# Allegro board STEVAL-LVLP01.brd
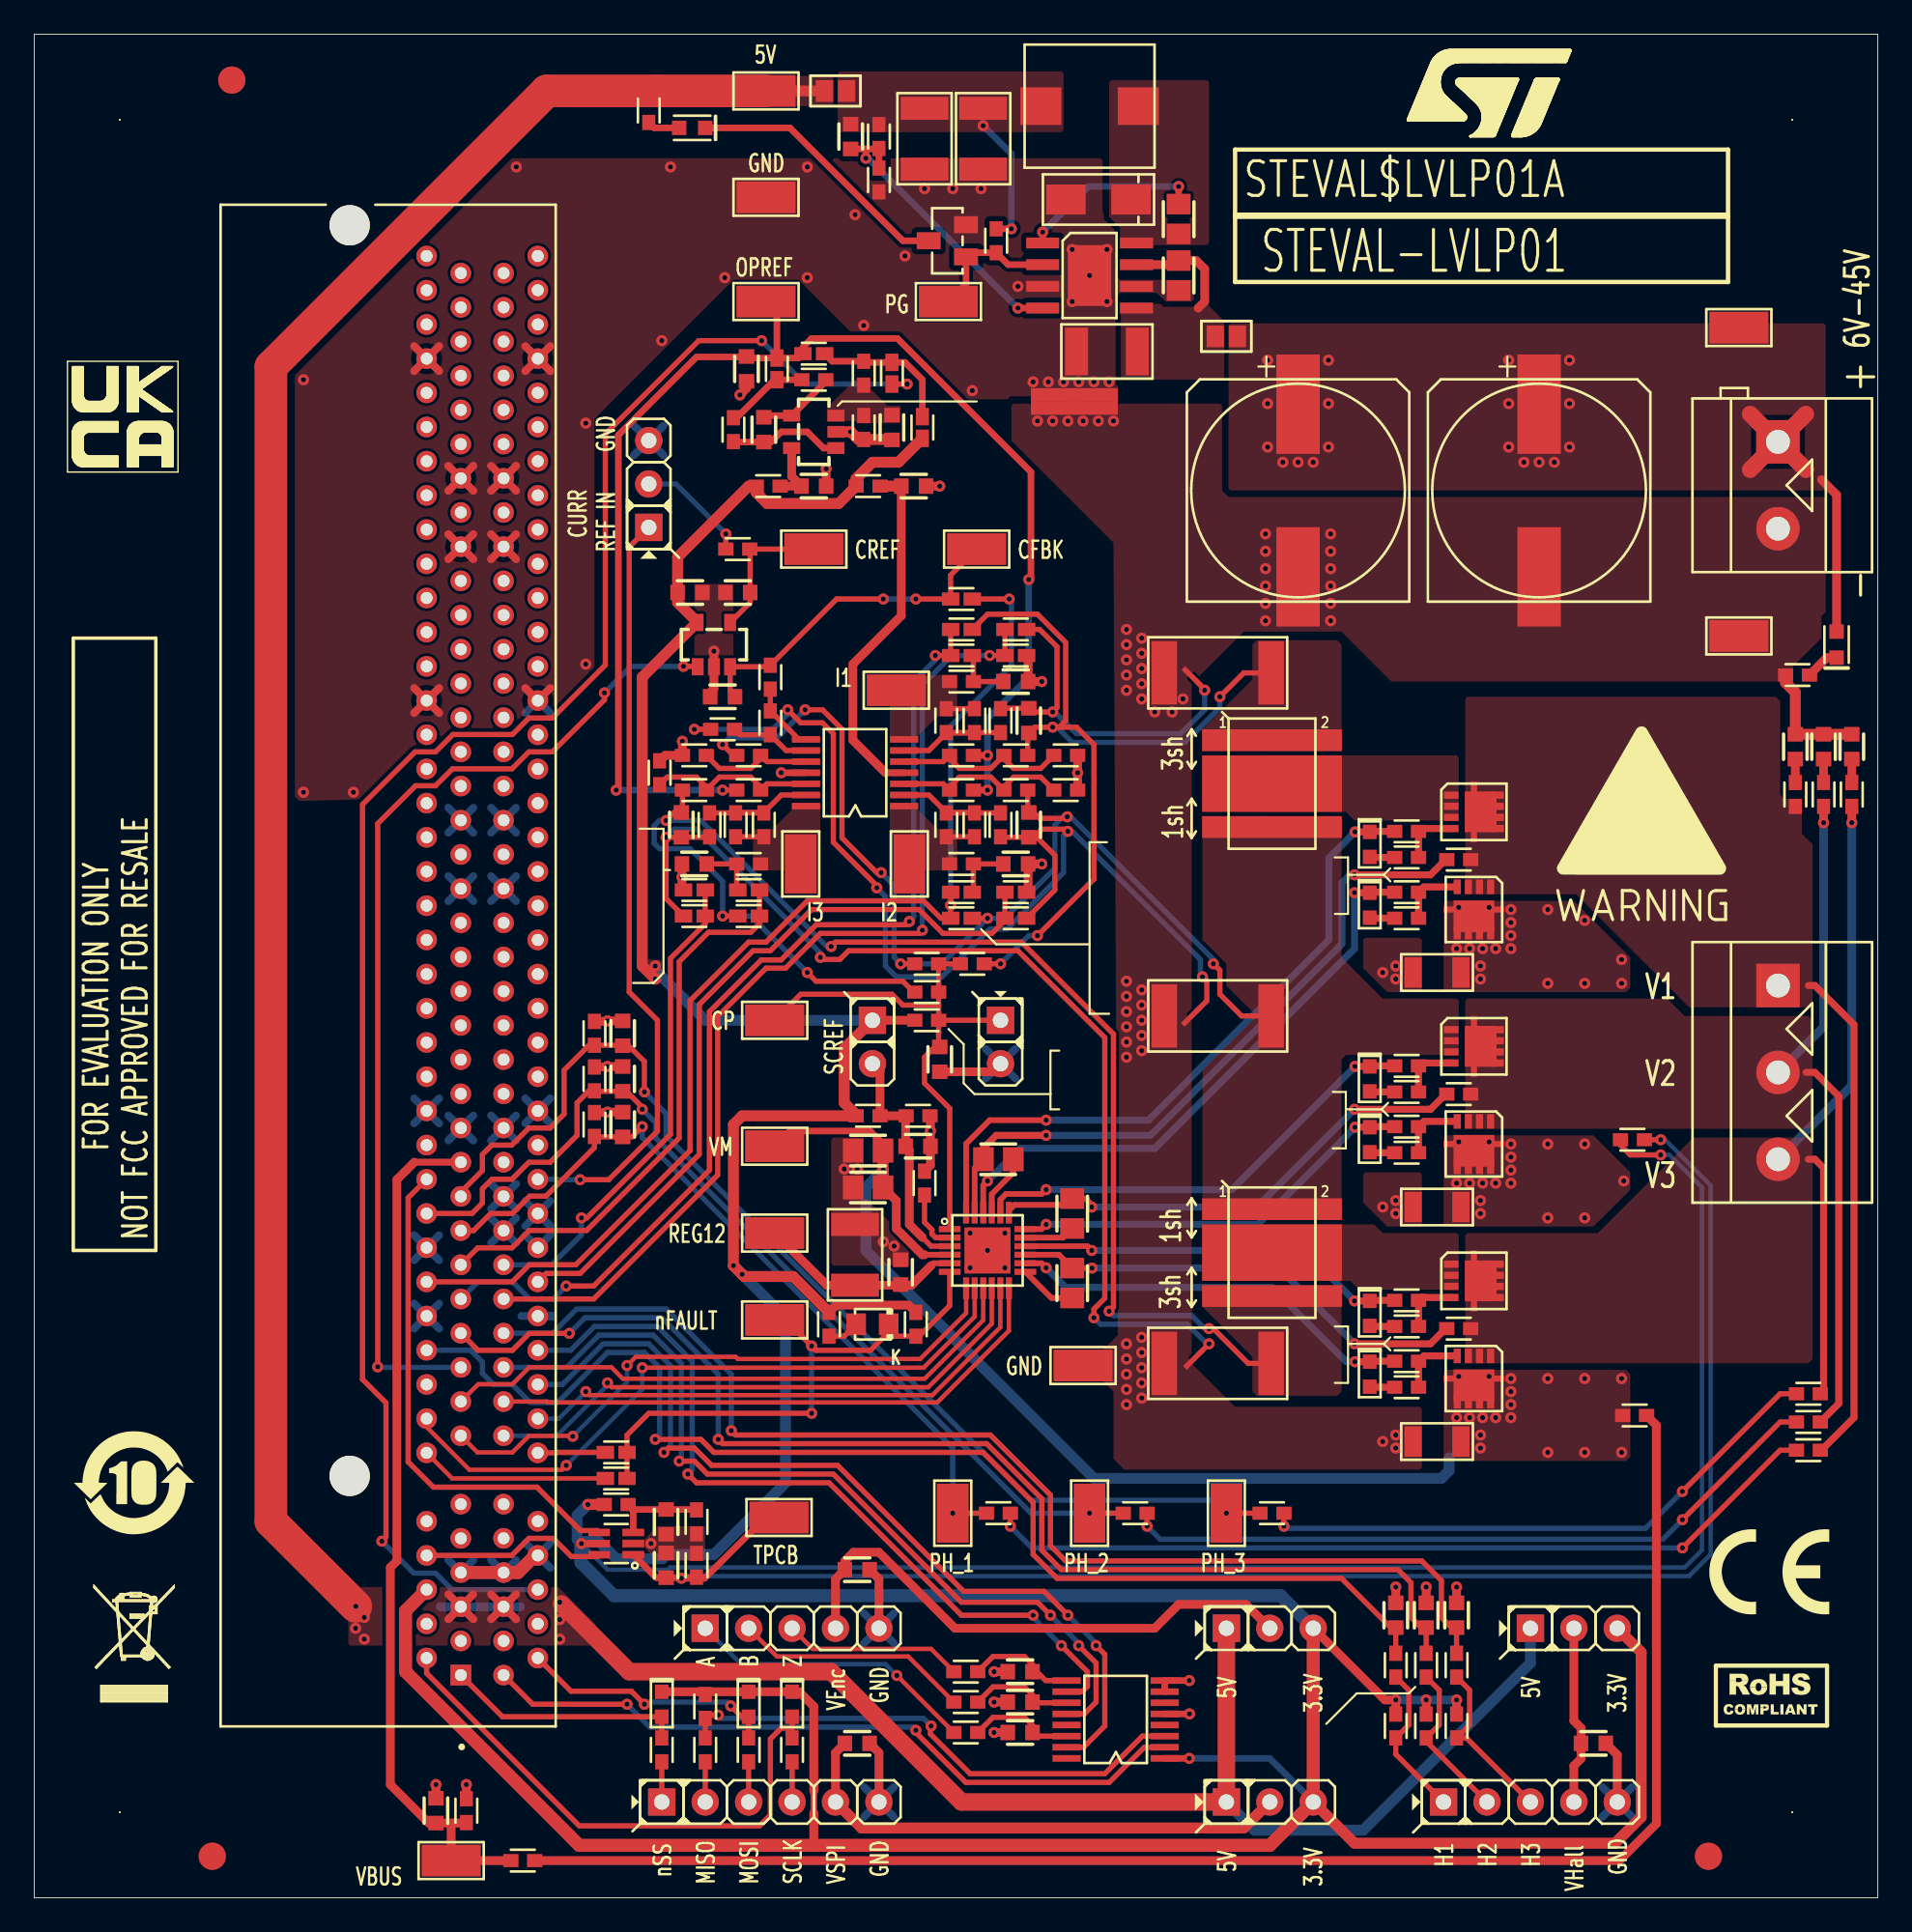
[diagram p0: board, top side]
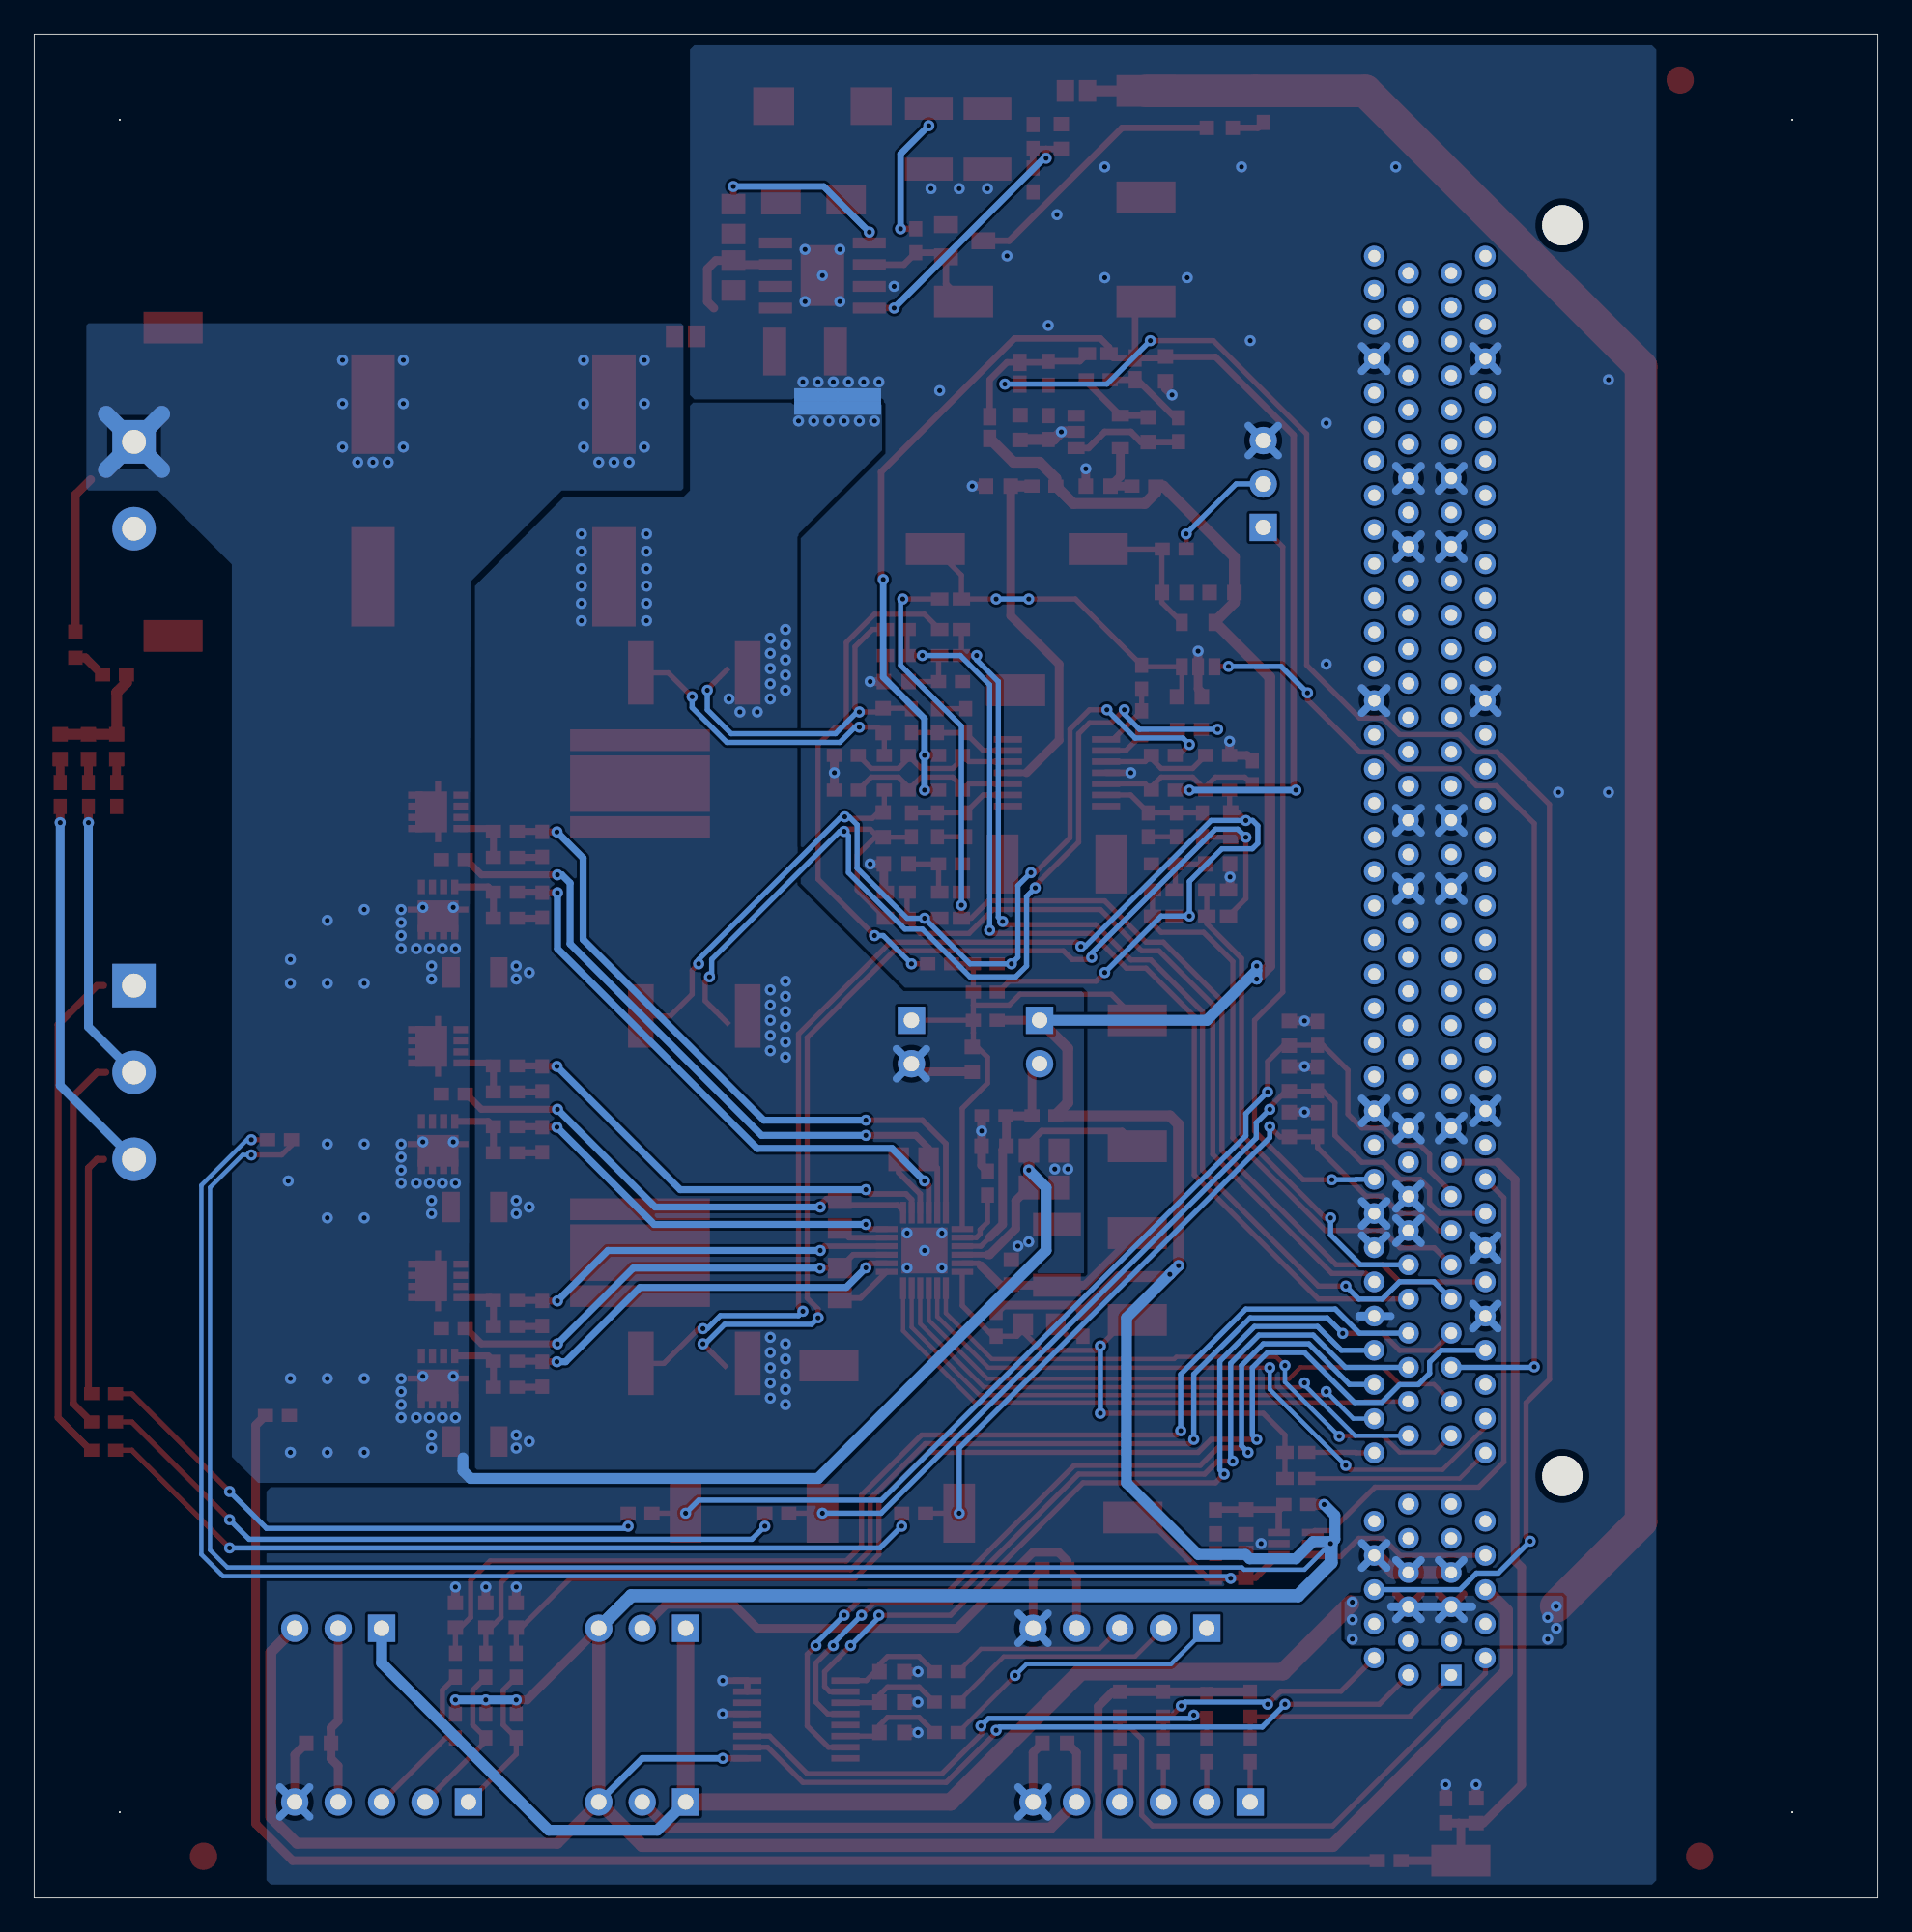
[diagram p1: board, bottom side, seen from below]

Outline 107.82 x 109 mm; copper layers: TOP, BOTTOM. Coordinates in mm from the lower left corner of the outline.
Outline path: 0,109 0,0 107.82,0 107.82,109 0,109

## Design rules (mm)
constraint set DEFAULT: min track width 0.2

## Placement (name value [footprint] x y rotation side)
C1  22uF  [C1210]  48.01 37.61 270 top
C2  220nF  [C0603]  50.67 36.59 90 top
C3  100nF  [C0805]  48.77 41.55 0 top
C4  1uF  [C0805]  48.77 43.71 0 top
C5  10nF  [C0603]  51.69 43.96 180 top
C6  1uF  [C0805]  56.39 43.2 0 top
C7  3.3nF  [C0603]  52.96 49.04 90 top
C8  1uF  [C0805]  60.71 35.96 90 top
C9  1uF  [C0805]  60.71 40.02 90 top
C10  220nF  [C1206]  82.04 54.12 90 top
C11  220nF  [C1206]  82.04 40.4 90 top
C12  220nF  [C1206]  82.04 26.69 90 top
C13  82nF  [C0603]  34.42 45.23 270 top
C14  82nF  [C0603]  34.42 47.9 270 top
C15  82nF  [C0603]  34.42 50.56 270 top
C16  NM  [C0603]  103 67.33 270 top
C17  NM  [C0603]  104.65 67.33 270 top
C18  NM  [C0603]  106.3 67.33 270 top
C19  100nF  [C0603]  51.44 82.57 0 top
C20  100nF  [C0603]  45.59 82.57 0 top
C21  1nF  [C0603]  58.17 68.85 270 top
C22  NM  [C0603]  57.4 71.14 180 top
C23  2.2u  [C0603]  41.66 89.43 270 top
C24  NM  [C0603]  50.16 86 270 top
C25  NM  [C0603]  42.67 85.87 90 top
C26  1nF  [C0603]  58.17 62.76 90 top
C27  NM  [C0603]  57.4 60.47 180 top
C28  100nF  [C0603]  38.35 76.34 0 top
C29  47p  [C0603]  40.26 70.25 0 top
C30  1nF  [C0603]  37.85 62.76 90 top
C31  10nF  [C0603]  41.15 76.34 0 top
C32  NM  [C0603]  38.61 60.47 0 top
C33  100nF  [C0805]  66.93 98.19 90 top
C34  47u  [C1210]  52.07 102.89 90 top
C35  47u  [C1210]  55.5 102.89 90 top
C36  1n  [C0603]  47.75 103.01 90 top
C37  100nF  [C0805]  66.93 94.89 270 top
C38  4.7uF  [C1210]  62.74 90.44 0 top
C39  47uF  [C-POL12_5X13_5]  88.01 82.31 0 top
C40  47uF  [C-POL12_5X13_5]  73.91 82.31 0 top
C41  82nF  [C0603]  23.5 5.1 270 top
C42  330nF  [C0603]  91.19 9.03 0 top
C43  2.2n  [C0603]  79.63 16.53 90 top
C44  2.2n  [C0603]  81.41 16.53 90 top
C45  2.2n  [C0603]  83.19 16.53 90 top
C46  1nF  [C0603]  57.66 9.67 0 top
C47  1nF  [C0603]  57.66 11.45 0 top
C48  330nF  [C0603]  48.13 19.19 0 top
C49  1nF  [C0603]  57.66 13.23 0 top
C50  10nF  [C0603]  36.96 19.45 270 top
C51  10nF  [C0603]  36.96 21.99 90 top
C52  330nF  [C0603]  48.13 9.03 0 top
D1  BAT30K  [SOD523]  78.11 58.06 270 top
D2  BAT30K  [SOD523]  78.11 44.34 270 top
D3  BAT30K  [SOD523]  78.11 30.62 270 top
D4  BAT30K  [SOD523]  78.11 61.61 270 top
D5  BAT30K  [SOD523]  78.11 47.9 270 top
D6  BAT30K  [SOD523]  78.11 34.18 270 top
D7  STPS2L60  [SMA]  62.24 99.33 270 top
D8  BAT30K  [SOD523]  36.7 11.32 270 top
D9  BAT30K  [SOD523]  41.78 11.32 270 top
D10  BAT30K  [SOD523]  44.32 11.32 270 top
J1  STRIP 1x2  [STRIP254P-M-2]  49.02 50.06 0 top
J2  STRIP 1x2  [STRIP254P-M-2]  56.52 50.06 0 top
J3  MORSV-508-3P_screw  [MORSV-508-3P]  101.98 48.28 270 top
J4  STRIP 1x3  [STRIP254P-M-3]  35.94 82.69 180 top
J5  STRIP 1x3  [STRIP254P-M-3]  90.04 15.77 90 top
J6  STRIP 1x5  [STRIP254P-M-5]  87.5 5.61 90 top
J7  MORSV-508-2P_screw  [MORSV-508-2P]  101.98 82.62 270 top
J8  STRIP 1x3  [STRIP254P-M-3]  72.26 15.77 90 top
J9  STRIP 1x5  [STRIP254P-M-5]  44.32 15.77 90 top
J10  STRIP 1x3  [STRIP254P-M-3]  72.26 5.61 90 top
J11  STRIP 1x6  [STRIP254P-M-6]  43.05 5.61 90 top
J12  PCIE-164-02-X-D-RA  [SAMTEC_PCIE-164-02-X-D-RA]  20.7 54.53 270 top
JP1  GND_node  [CORTONOSOLDER200MILS]  60.83 87.52 270 bottom
JP2  GND_node  [CORTONOSOLDER200MILS]  60.83 87.52 270 top
JP3  CurrentSense  [CURRENTSENSE-12]  67.73 71.41 315 top
JP4  CurrentSense  [CURRENTSENSE-12]  67.69 51.58 45 top
JP5  CurrentSense  [CURRENTSENSE-12]  67.82 31.51 45 top
L1  10uH  [CLF7045NI-D-TDK]  61.72 104.79 180 top
LED1  RED  [LED-0805]  49.02 33.55 180 top
LED2  GREEN  [LED-0603]  38.48 103.52 180 top
LED3  GREEN  [LED-0603]  105.41 73.3 90 top
NOREF  -  [unnamed]  10.41 2.43 0 top
NOREF#2  -  [unnamed]  11.56 106.32 0 top
NOREF#3  -  [#2]  101.52 11.82 0 top
NOREF#4  -  [#2]  -0.25 -84.82 0 top
NOREF#5  -  [unnamed]  97.92 2.43 0 top
NOREF#6  -  [#2]  93.98 60.6 0 top
NOREF#7  -  [#2]  97.98 16.58 0 top
NOREF#8  -  [unnamed]  5 104 90 top
NOREF#9  -  [#2]  2.32 21.26 0 top
NOREF#10  -  [#2]  217.55 28.21 0 top
NOREF#11  -  [#2]  107.82 0 90 top
NOREF#12  -  [#2]  0 109 0 top
NOREF#13  -  [unnamed]  5 5 90 top
NOREF#14  -  [unnamed]  102.82 5 90 top
NOREF#15  -  [unnamed]  102.82 104 90 top
NOREF#16  -  [#2]  80.25 103.4 0 top
NOREF#17  -  [#2]  132.72 56.41 0 top
NOREF#18  -  [#2]  5.8 15.73 0 top
NTC1  10k  [R0603]  93.47 44.34 90 top
Q1  STL8N10F7  [PFLAT_3_3X3_3]  84.2 57.8 270 top
Q2  STL8N10F7  [PFLAT_3_3X3_3]  84.2 44.09 270 top
Q3  STL8N10F7  [PFLAT_3_3X3_3]  84.2 30.37 270 top
Q4  STL8N10F7  [PFLAT_3_3X3_3]  84.2 63.52 0 top
Q5  STL8N10F7  [PFLAT_3_3X3_3]  84.2 49.8 0 top
Q6  STL8N10F7  [PFLAT_3_3X3_3]  84.2 36.09 0 top
Q7  BSS123  [SOT23]  53.4 96.92 90 top
R1  33k  [R0603]  48.77 45.74 270 top
R2  470  [R0603]  46.48 33.55 180 top
R3  39k  [R0603]  51.56 33.55 180 top
R4  12k  [R0603]  51.69 45.74 270 top
R5  0  [R0603]  52.07 41.8 0 top
R6  5.1k  [R0603]  52.2 51.33 90 top
R7  2.2k  [R0603]  54.86 54.63 90 top
R8  2.2k  [R0603]  52.2 54.63 270 top
R9  2.2k  [R0603]  52.2 52.98 270 top
R10  100  [R0603]  80.26 58.82 90 top
R11  100  [R0603]  80.26 45.1 90 top
R12  100  [R0603]  80.26 31.39 90 top
R13  39  [R0603]  80.26 57.29 90 top
R14  39  [R0603]  80.26 43.58 90 top
R15  39  [R0603]  80.26 29.86 90 top
R16  0  [R0603]  83.31 60.72 90 top
R17  0  [R0603]  83.31 47.01 90 top
R18  0  [R0603]  83.31 33.29 90 top
R19  100  [R0603]  80.26 62.37 90 top
R20  100  [R0603]  80.26 48.66 90 top
R21  100  [R0603]  80.26 34.94 90 top
R22  39  [R0603]  80.26 60.85 90 top
R23  39  [R0603]  80.26 47.13 90 top
R24  39  [R0603]  80.26 33.42 90 top
R25  15m  [R2512]  69.22 71.65 0 top
R26  15m  [R2512]  69.22 51.58 0 top
R27  15m  [R2512]  69.22 31.26 0 top
R28  68k  [R0603]  103.76 26.18 270 top
R29  27k  [R0603]  56.39 22.5 270 top
R30  68k  [R0603]  103.76 27.83 270 top
R31  27k  [R0603]  64.39 22.5 270 top
R32  68k  [R0603]  103.76 29.48 270 top
R33  27k  [R0603]  72.39 22.5 270 top
R34  NM  [R0603]  103 64.53 0 top
R35  3.9k  [R0603]  32.77 45.23 0 top
R36  NM  [R0603]  104.65 64.53 0 top
R37  3.9k  [R0603]  32.77 47.9 0 top
R38  NM  [R0603]  106.3 64.53 0 top
R39  3.9k  [R0603]  32.77 50.56 0 top
R40  4.7  [R0603]  48.77 82.57 90 top
R41  4.7  [R0603]  42.93 82.57 90 top
R42  30k  [R0603]  54.23 66.82 270 top
R43  0R  [J0603]  54.23 74.19 270 top
R44  1k  [R0603]  57.4 66.82 90 top
R45  0  [R0603]  54.23 71.14 270 top
R46  NM  [J0603]  54.23 72.66 270 top
R47  1k  [R0603]  56.52 68.85 180 top
R48  30k  [R0603]  60.33 66.82 90 top
R49  NM  [J0603]  57.4 72.66 90 top
R50  NM  [J0603]  50.16 89.17 0 top
R51  0R  [J0603]  51.94 86 0 top
R52  0  [J0603]  45.59 90.31 270 top
R53  30k  [R0603]  54.99 68.85 0 top
R54  0R  [J0603]  57.4 74.19 90 top
R55  NM  [R0603]  48.51 89.17 180 top
R56  30k  [R0603]  53.34 68.85 0 top
R57  NM  [J0603]  43.43 89.43 0 top
R58  NM  [R0603]  40.89 85.87 180 top
R59  NM  [R0603]  48.51 86 180 top
R60  NM  [J0603]  54.23 75.96 90 top
R61  30k  [R0603]  54.23 64.79 270 top
R62  0R  [J0603]  54.23 57.29 270 top
R63  1k  [R0603]  57.4 64.79 90 top
R64  0  [R0603]  54.23 60.47 270 top
R65  NM  [J0603]  54.23 58.82 270 top
R66  NM  [R0603]  45.59 88.79 90 top
R67  1k  [R0603]  56.52 62.76 0 top
R68  30k  [R0603]  60.33 64.79 90 top
R69  NM  [J0603]  57.4 58.82 90 top
R70  30k  [R0603]  53.34 62.76 180 top
R71  0R  [J0603]  57.4 57.29 90 top
R72  30k  [R0603]  54.99 62.76 180 top
R73  1k  [R0603]  41.78 66.82 270 top
R74  10k  [R0603]  43.05 71.39 0 top
R75  1k  [R0603]  40.26 68.34 270 top
R76  22k  [R0603]  38.61 66.82 270 top
R77  22k  [R0603]  43.05 68.72 180 top
R78  30k  [R0603]  41.78 64.79 90 top
R79  0R  [J0603]  41.78 57.42 90 top
R80  1k  [R0603]  38.61 64.79 270 top
R81  10k  [R0603]  41.15 78.88 270 top
R82  0  [R0603]  41.78 60.47 90 top
R83  NM  [J0603]  41.78 58.95 90 top
R84  1k  [R0603]  39.5 62.76 0 top
R85  30k  [R0603]  36.58 65.8 180 top
R86  NM  [J0603]  38.61 58.95 270 top
R87  30k  [R0603]  41.02 62.76 180 top
R88  0R  [J0603]  38.61 57.42 270 top
R89  30k  [R0603]  42.67 62.76 180 top
R90  0R  [J0805]  69.72 91.33 90 top
R91  47k  [R0603]  56.26 96.92 180 top
R92  0R  [J0805]  46.86 105.68 270 top
R93  4.7k  [R0603]  49.4 103.01 180 top
R94  1k  [R0603]  35.94 104.54 180 top
R95  1.5k  [R0603]  49.4 100.47 180 top
R96  4.7k  [R0603]  79.63 10.05 180 top
R97  4.7k  [R0603]  81.41 10.05 180 top
R98  4.7k  [R0603]  83.19 10.05 180 top
R99  68k  [R0603]  93.6 28.21 90 top
R100  27k  [R0603]  28.57 2.18 270 top
R101  3.3k  [R0603]  79.63 13.61 0 top
R102  3.3k  [R0603]  81.41 13.61 0 top
R103  3.9k  [R0603]  25.27 5.1 0 top
R104  3.3k  [R0603]  83.19 13.61 0 top
R105  15k  [R0603]  103.12 71.52 90 top
R106  330  [R0603]  54.48 9.67 270 top
R107  330  [R0603]  54.48 11.45 270 top
R108  330  [R0603]  54.48 13.23 270 top
R109  910  [R0603]  38.73 19.45 0 top
R110  22k  [R0603]  34.04 23 270 top
R111  10k  [R0603]  38.73 21.99 180 top
R112  22k  [R0603]  39.24 11.19 0 top
R113  100  [R0603]  36.7 8.65 0 top
R114  100  [R0603]  39.24 8.65 0 top
R115  100  [R0603]  41.78 8.65 0 top
R116  100  [R0603]  44.32 8.65 0 top
R117  NM  [J0603]  34.04 24.53 90 top
R118  0R  [J0603]  34.04 26.05 270 top
SB1  Power_Solder_Bridge  [254-PITCH_HEADER-2X3-JUMP]  72.39 65.17 0 top
SB2  Power_Solder_Bridge  [254-PITCH_HEADER-2X3-JUMP]  72.39 37.74 0 top
TP1  TP-SMD-S1751-46R  [S1751-46R]  43.31 38.88 180 top
TP2  TP-SMD-S1751-46R  [S1751-46R]  43.31 43.96 180 top
TP3  TP-SMD-S1751-46R  [S1751-46R]  43.31 33.8 0 top
TP4  TP-SMD-S1751-46R  [S1751-46R]  43.31 51.33 180 top
TP5  TP-SMD-S1751-46R  [S1751-46R]  61.34 31.13 0 top
TP6  TP-SMD-S1751-46R  [S1751-46R]  53.72 22.5 90 top
TP7  TP-SMD-S1751-46R  [S1751-46R]  61.72 22.5 90 top
TP8  TP-SMD-S1751-46R  [S1751-46R]  69.72 22.5 90 top
TP9  TP-SMD-S1751-46R  [S1751-46R]  50.42 70.63 180 top
TP10  TP-SMD-S1751-46R  [S1751-46R]  42.8 93.36 0 top
TP11  TP-SMD-S1751-46R  [S1751-46R]  51.18 60.47 270 top
TP12  TP-SMD-S1751-46R  [S1751-46R]  55.12 78.88 180 top
TP13  TP-SMD-S1751-46R  [S1751-46R]  44.83 60.47 270 top
TP14  TP-SMD-S1751-46R  [S1751-46R]  45.59 78.88 180 top
TP15  TP-SMD-S1751-46R  [S1751-46R]  42.8 105.68 180 top
TP16  TP-SMD-S1751-46R  [S1751-46R]  42.8 99.46 0 top
TP17  TP-SMD-S1751-46R  [S1751-46R]  53.47 93.36 0 top
TP18  TP-SMD-S1751-46R  [S1751-46R]  99.69 91.84 0 top
TP19  TP-SMD-S1751-46R  [S1751-46R]  24.38 2.18 0 top
TP20  TP-SMD-S1751-46R  [S1751-46R]  99.69 73.8 0 top
TP21  TP-SMD-S1751-46R  [S1751-46R]  43.56 22.24 0 top
U1  STDRIVE101  [QFN24-4X4]  55.75 37.86 270 top
U2  TSV994  [TSSOP14]  48.01 65.8 180 top
U3  NM  [SOT23-5L]  45.59 85.74 90 top
U4  TS3021ILT  [SOT23-5L]  39.75 73.3 0 top
U5  ST1S14PHR  [SO8-EP-9]  61.72 94.89 0 top
U6  CD74HC4050  [TSSOP16]  63.25 10.43 180 top
U7  Value  [SOT323-6L]  34.04 20.72 90 top

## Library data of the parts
C1 C34 C35 C38 = C-1210
C2 C5 C7 C13-C32 C36 C41-C52 = C-0603
C3 C6 C8 C9 C33 C37 = C-0805
C4 C10-C12 = C-1206
C39 C40 = C_EL-DIAM10
D1-D6 D8-D10 = BAT30K
D7 = STPS2L30A
J1 J2 = STRIP 1x2
J3 = MORSV-508-3P_screw
J4 J5 J8 J10 = STRIP 1x3
J6 J9 = STRIP 1x5
J7 = MORSV-508-2P_screw_0
J11 = STRIP 1x6
J12 = PCIE-164-02-X-D-RA
JP1-JP5 = CurrentSense
L1 = INDUCTOR
LED1 = LED-0805
LED2 LED3 = LED-0603-GREEN-WE
NTC1 = NTC-NCP18XH103F03RB
Q1-Q6 = STL11N6F7
Q7 = BSS123
R1-R24 R28-R42 R44 R45 R47 R48 R53 R55 R56 R58 R59 R61 R63 R64 R66-R68 R70 R72-R78 R80-R82 R84 R85 R87 R89 R91 R93-R116 = R-0603
R25-R27 = R-2512
R43 R46 R49-R52 R54 R57 R60 R62 R65 R69 R71 R79 R83 R86 R88 R117 R118 = JUMPER-R0603
R90 R92 = JUMPER-R0805
SB1 SB2 = Power_Solder_Bridge
TP1-TP21 = TP-SMD-S1751-46R
U1 = STDRIVE101
U2 = TSV994IPT
U3 = TS461CLT
U4 = TS3021ILT
U5 = ST1S14PHR
U6 = CD74HC4050PW
U7 = STG3157CTR

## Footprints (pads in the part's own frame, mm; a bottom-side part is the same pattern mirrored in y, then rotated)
254-PITCH_HEADER-2X3-JUMP
  rect 8.179x1.27 smd: 1(0,2.54) 3(0,-2.54)
  rect 8.179x3.302 smd: 2(0,0)
C0603
  rect 0.85x0.9 smd: 1(-0.725,0) 2(0.725,0)
C0805
  rect 1.2x1.4 smd: 1(-0.875,0) 2(0.875,0)
C1206
  rect 1.778x1.016 smd: 1(0,1.397) 2(0,-1.397)
C1210
  rect 1.346x2.794 smd: 1(-1.778,0) 2(1.778,0)
C-POL12_5X13_5
  rect 2.54x5.817 smd: 1(0,5.05) 2(0,-5.05)
CLF7045NI-D-TDK
  rect 2.4x2.2 smd: 1(-2.85,0) 2(2.85,0)
CORTONOSOLDER200MILS
  rect 0.787x5.08 smd: 1(-0.127,0) 2(0.127,0)
CURRENTSENSE-12
  rect 0.762x0.305 smd: 1(-0.356,0) 2(0.356,0)
J0603
  rect 0.762x1.016 smd: 1(0,0.635) 2(0,-0.635)
J0805
  rect 1.27x1.016 smd: 1(0,0.648) 2(0,-0.648)
LED-0603
  rect 0.838x0.838 smd: 1(-0.762,0) 2(0.762,0)
LED-0805
  rect 1.143x1.27 smd: 1(-0.953,0) 2(0.953,0)
MORSV-508-2P
  rect 2.54x2.54 hole 1.397: 1(-2.54,0)
  round 2.54 hole 1.397: 2(2.54,0)
MORSV-508-3P
  rect 2.54x2.54 hole 1.397: 1(-5.08,0)
  round 2.54 hole 1.397: 2(0,0) 3(5.08,0)
PFLAT_3_3X3_3
  rect 0.85x0.42 smd: 1(-1.325,0.975) 2(-1.325,0.325) 3(-1.325,-0.325) 4(-1.325,-0.975) 5(1.325,-0.975) 6(1.325,-0.325) 7(1.325,0.325) 8(1.325,0.975)
QFN24-4X4
  rect 0.356x1.27 smd: 1(-1.25,-2.21) 2(-0.75,-2.21) 3(-0.25,-2.21) 4(0.25,-2.21) 5(0.75,-2.21) 6(1.25,-2.21) 13(1.25,2.21) 14(0.75,2.21) 15(0.25,2.21) 16(-0.25,2.21) 17(-0.75,2.21) 18(-1.25,2.21)
  rect 1.27x0.356 smd: 7(2.21,-1.25) 8(2.21,-0.75) 9(2.21,-0.25) 10(2.21,0.25) 11(2.21,0.75) 12(2.21,1.25) 19(-2.21,1.25) 20(-2.21,0.75) 21(-2.21,0.25) 22(-2.21,-0.25) 23(-2.21,-0.75) 24(-2.21,-1.25)
  rect 2.692x2.692 smd: 25(0,0)
R0603
  rect 0.762x0.889 smd: 1(0,0.699) 2(0,-0.699)
R2512
  rect 1.499x3.708 smd: 1(-3.124,0) 2(3.124,0)
S1751-46R
  rect 3.454x1.854 smd: 1(0,0)
SAMTEC_PCIE-164-02-X-D-RA
  round 2.35 hole 2.35 unplated: (-43.3,-2.25) (29.85,-2.25)
  rect 1.208x1.208 hole 0.7: A01(41.5,4.25)
  round 1.208 hole 0.7: A02(40.5,2.25) A03(39.5,4.25) A04(38.5,2.25) A05(37.5,4.25) A06(36.5,2.25) A07(35.5,4.25) A08(34.5,2.25) A09(33.5,4.25) A10(32.5,2.25) A11(31.5,4.25) A12(28.5,2.25) A13(27.5,4.25) A14(26.5,2.25) A15(25.5,4.25) A16(24.5,2.25) A17(23.5,4.25) A18(22.5,2.25) A19(21.5,4.25) A20(20.5,2.25) A21(19.5,4.25) A22(18.5,2.25) A23(17.5,4.25) A24(16.5,2.25) A25(15.5,4.25) A26(14.5,2.25) A27(13.5,4.25) A28(12.5,2.25) A29(11.5,4.25) A30(10.5,2.25) A31(9.5,4.25) A32(8.5,2.25) A33(7.5,4.25) A34(6.5,2.25) A35(5.5,4.25) A36(4.5,2.25) A37(3.5,4.25) A38(2.5,2.25) A39(1.5,4.25) A40(0.5,2.25) A41(-0.5,4.25) A42(-1.5,2.25) A43(-2.5,4.25) A44(-3.5,2.25) A45(-4.5,4.25) A46(-5.5,2.25) A47(-6.5,4.25) A48(-7.5,2.25) A49(-8.5,4.25) A50(-9.5,2.25) A51(-10.5,4.25) A52(-11.5,2.25) A53(-12.5,4.25) A54(-13.5,2.25) A55(-14.5,4.25) A56(-15.5,2.25) A57(-16.5,4.25) A58(-17.5,2.25) A59(-18.5,4.25) A60(-19.5,2.25) A61(-20.5,4.25) A62(-21.5,2.25) A63(-22.5,4.25) A64(-23.5,2.25) A65(-24.5,4.25) A66(-25.5,2.25) A67(-26.5,4.25) A68(-27.5,2.25) A69(-28.5,4.25) A70(-29.5,2.25) A71(-30.5,4.25) A72(-31.5,2.25) A73(-32.5,4.25) A74(-33.5,2.25) A75(-34.5,4.25) A76(-35.5,2.25) A77(-36.5,4.25) A78(-37.5,2.25) A79(-38.5,4.25) A80(-39.5,2.25) A81(-40.5,4.25) A82(-41.5,2.25) B01(41.5,6.75) B02(40.5,8.75) B03(39.5,6.75) B04(38.5,8.75) B05(37.5,6.75) B06(36.5,8.75) B07(35.5,6.75) B08(34.5,8.75) B09(33.5,6.75) B10(32.5,8.75) B11(31.5,6.75) B12(28.5,8.75) B13(27.5,6.75) B14(26.5,8.75) B15(25.5,6.75) B16(24.5,8.75) B17(23.5,6.75) B18(22.5,8.75) B19(21.5,6.75) B20(20.5,8.75) B21(19.5,6.75) B22(18.5,8.75) B23(17.5,6.75) B24(16.5,8.75) B25(15.5,6.75) B26(14.5,8.75) B27(13.5,6.75) B28(12.5,8.75) B29(11.5,6.75) B30(10.5,8.75) B31(9.5,6.75) B32(8.5,8.75) B33(7.5,6.75) B34(6.5,8.75) B35(5.5,6.75) B36(4.5,8.75) B37(3.5,6.75) B38(2.5,8.75) B39(1.5,6.75) B40(0.5,8.75) B41(-0.5,6.75) B42(-1.5,8.75) B43(-2.5,6.75) B44(-3.5,8.75) B45(-4.5,6.75) B46(-5.5,8.75) B47(-6.5,6.75) B48(-7.5,8.75) B49(-8.5,6.75) B50(-9.5,8.75) B51(-10.5,6.75) B52(-11.5,8.75) B53(-12.5,6.75) B54(-13.5,8.75) B55(-14.5,6.75) B56(-15.5,8.75) B57(-16.5,6.75) B58(-17.5,8.75) B59(-18.5,6.75) B60(-19.5,8.75) B61(-20.5,6.75) B62(-21.5,8.75) B63(-22.5,6.75) B64(-23.5,8.75) B65(-24.5,6.75) B66(-25.5,8.75) B67(-26.5,6.75) B68(-27.5,8.75) B69(-28.5,6.75) B70(-29.5,8.75) B71(-30.5,6.75) B72(-31.5,8.75) B73(-32.5,6.75) B74(-33.5,8.75) B75(-34.5,6.75) B76(-35.5,8.75) B77(-36.5,6.75) B78(-37.5,8.75) B79(-38.5,6.75) B80(-39.5,8.75) B81(-40.5,6.75) B82(-41.5,8.75)
SMA
  rect 1.753x2.311 smd: 1(0,1.905) 2(0,-1.905)
SO8-EP-9
  rect 1.93x0.635 smd: 1(-2.743,1.905) 2(-2.743,0.635) 3(-2.743,-0.635) 4(-2.743,-1.905) 5(2.743,-1.905) 6(2.743,-0.635) 7(2.743,0.635) 8(2.743,1.905)
  rect 2.54x3.556 smd: 9(0,0)
SOD523
  rect 0.838x0.8 smd: 1(-0.731,0) 2(0.731,0)
SOT23
  rect 0.991x1.397 smd: 1(-0.94,-1.092) 2(0.94,-1.092) 3(0,1.092)
SOT23-5L
  rect 0.69x1 smd: 1(-0.95,-1.295) 2(0,-1.295) 3(0.95,-1.295) 4(0.95,1.295) 5(-0.95,1.295)
SOT323-6L
  rect 0.432x1.27 smd: 1(-0.65,-1) 2(0,-1) 3(0.65,-1) 4(0.65,1) 5(0,1) 6(-0.65,1)
STRIP254P-M-2
  rect 1.6x1.6 hole 0.9: 1(0,1.27)
  round 1.6 hole 0.9: 2(0,-1.27)
STRIP254P-M-3
  rect 1.6x1.6 hole 0.9: 1(0,2.54)
  round 1.6 hole 0.9: 2(0,0) 3(0,-2.54)
STRIP254P-M-5
  rect 1.6x1.6 hole 0.9: 1(0,5.08)
  round 1.6 hole 0.9: 2(0,2.54) 3(0,0) 4(0,-2.54) 5(0,-5.08)
STRIP254P-M-6
  rect 1.6x1.6 hole 0.9: 1(0,6.35)
  round 1.6 hole 0.9: 2(0,3.81) 3(0,1.27) 4(0,-1.27) 5(0,-3.81) 6(0,-6.35)
TSSOP14
  rect 1.651x0.381 smd: 1(-2.87,1.951) 2(-2.87,1.3) 3(-2.87,0.65) 4(-2.87,0) 5(-2.87,-0.65) 6(-2.87,-1.3) 7(-2.87,-1.951) 8(2.87,-1.951) 9(2.87,-1.3) 10(2.87,-0.65) 11(2.87,0) 12(2.87,0.65) 13(2.87,1.3) 14(2.87,1.951)
TSSOP16
  rect 1.651x0.381 smd: 1(-2.87,2.276) 2(-2.87,1.626) 3(-2.87,0.975) 4(-2.87,0.325) 5(-2.87,-0.325) 6(-2.87,-0.975) 7(-2.87,-1.626) 8(-2.87,-2.276) 9(2.87,-2.276) 10(2.87,-1.626) 11(2.87,-0.975) 12(2.87,-0.325) 13(2.87,0.325) 14(2.87,0.975) 15(2.87,1.626) 16(2.87,2.276)
unnamed
  round 1.6 smd: (0,0)

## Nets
5V: J5.1 J8.1 J10.1 J12.A05 J12.B05 R92.2 R94.2 TP15.1
12V: C1.2 C2.1 TP1.1 U1.5
GND: C1.1 C2.2 C3.1 C4.1 C5.1 C7.1 C10.1 C11.1 C12.1 C16.1 C17.1 C18.1 C39.2 C40.2 J2.2 J7.2 JP1.2 JP2.2 JP3.1 JP4.1 JP5.1 R4.1 R5.1 R25.1 R26.1 R27.1 R105.1 TP5.1 TP20.1 U1.25
GND_SIGNAL: C13.1 C14.1 C15.1 C19.2 C20.2 C22.1 C23.2 C24.2 C27.1 C28.2 C29.1 C31.1 C32.1 C34.1 C35.1 C37.2 C38.1 C41.1 C42.2 C43.2 C44.2 C45.2 C46.1 C47.1 C48.2 C49.1 C50.1 C51.1 C52.2 D7.2 J4.3 J6.5 J9.5 J11.6 J12.A07 J12.A20 J12.A24 J12.A31 J12.A32 J12.A45 J12.A49 J12.A56 J12.A65 J12.A69 J12.A76 J12.B07 J12.B08 J12.B20 J12.B24 J12.B25 J12.B26 J12.B27 J12.B31 J12.B32 J12.B45 J12.B49 J12.B56 J12.B65 J12.B69 J12.B76 JP1.1 JP2.1 Q7.2(SOURCE) R35.1 R37.1 R39.1 R48.2 R49.2 R59.1 R68.2 R69.2 R76.2 R85.2 R86.2 R95.1 R103.1 R109.1 R111.1 TP16.1 U2.11 U3.2(V-) U4.2(VCC-) U5.3 U5.6 U5.9 U6.5 U6.7 U6.8 U7.2
V1: J3.1 Q1.1 Q1.2 Q1.3(S#3) Q4.5 Q4.6 Q4.7 Q4.8 R16.2 R28.1 R34.2
V2: J3.2 Q2.1 Q2.2 Q2.3(S#3) Q5.5 Q5.6 Q5.7 Q5.8 R17.2 R30.1 R36.2
V3: J3.3 Q3.1 Q3.2 Q3.3(S#3) Q6.5 Q6.6 Q6.7 Q6.8 R18.2 R32.1 R38.2
VBUS: C41.2 J12.A29 R100.2 R103.2 TP19.1
VDD: C28.1 D8.1(C) D9.1(C) D10.1(C) J1.1 J5.3 J8.3 J10.3 J12.A06 NTC1.1 R1.2 R2.2 R3.2 R6.1 R40.1 R41.1 R51.2 R96.2 R97.2 R98.2 R110.2 R112.1 U4.5 U6.1 U7.5(VCC)
VDD_C: C20.1 R41.2 U3.5
VDD_F: C19.1 R40.2 U2.4
BUCK_OUT: C34.2 C35.2 C36.2 L1.2 R91.2 R92.1 R93.2
CFBK: C29.2 R60.1 R74.1 TP12.1 U4.3
CP_DRV: C7.2 J2.1 R6.2 R7.1 R8.1 R9.1 TP4.1 U1.1
CURR_REF: J4.1 J12.B28
ENCA: J12.B16 U6.15(6Y)
ENCB: J12.B17 U6.12
ENCZ: J12.B18 U6.10
ETR: J12.A17 U4.1
FB: C36.1 R93.1 R95.2 U5.4
GHS1: D1.1(C) R10.1 U1.22
GHS2: D2.1(C) R11.1 U1.18
GHS3: D3.1(C) R12.1 U1.14
GLS1: D4.1(C) R19.1 U1.24
GLS2: D5.1(C) R20.1 U1.20
GLS3: D6.1(C) R21.1 U1.16
H1: C43.1 J12.A18 R101.1
H2: C44.1 J12.A19 R102.1
H3: C45.1 J12.B19 R104.1
ID_ENABLE_N: J12.A08 U7.6
INH1: J12.A13 U1.7
INH2: J12.A14 U1.8
INH3: J12.A15 U1.9
INL1: J12.B13 U1.10
INL2: J12.B14 U1.11
INL3: J12.B15 U1.12
ISNS1N: J12.B21 R49.1 R54.1
ISNS1P: J12.A21 R43.2 R46.2
ISNS2N: J12.B22 R69.1 R71.1
ISNS2P: J12.A22 R60.2 R62.2 R65.2
ISNS3N: J12.B23 R86.1 R88.1
ISNS3P: J12.A23 R79.2 R83.2
LSS1: Q4.1 Q4.2 Q4.3(S#3) SB1.2
LSS3: Q6.1 Q6.2 Q6.3(S#3) SB2.2
NFAULT: LED1.1 R3.1 R117.2 R118.1 TP3.1 U1.6
OPREF: C23.1 R42.1 R52.2 R57.1 R61.1 R78.1 TP10.1
OUT1: C6.1 R16.1 U1.23
OUT2: C9.2 R17.1 U1.19
OUT3: C8.2 R18.1 U1.15
P_GOOD: Q7.1 R91.1 TP17.1 U5.2
SCREF: C5.2 J1.2 R1.1 R4.2 U1.3
SHUNT1N: C21.1 JP3.2 R47.2 R54.2
SHUNT1P: C21.2 R7.2 R25.2 R43.1 R44.2 SB1.1
SHUNT2N: C26.1 JP4.2 R67.2 R71.2 R75.2
SHUNT2P: C26.2 Q5.1 Q5.2 Q5.3(S#3) R8.2 R26.2 R62.1 R63.2 R73.2 SB1.3 SB2.1
SHUNT3N: C30.1 JP5.2 R84.2 R88.2
SHUNT3P: C30.2 R9.2 R27.2 R79.1 R80.2 SB2.3
SPI_MISO: J12.B01 U6.2
SPI_MOSI: D9.2 J12.B02 R115.1
SPI_NSS: D8.2 J12.A01 R113.1
SPI_SCK: D10.2 J12.A02 R116.1
TEMP_ID: J12.A28 U7.4
TPCB: C50.2 NTC1.2 R109.2 TP21.1 U7.1
VM: C3.2 C4.2 C10.2 C11.2 C12.2 C39.1(POS) C40.1(POS) J7.1 LED3.2 Q1.5 Q1.6 Q1.7 Q1.8 Q2.5 Q2.6 Q2.7 Q2.8 Q3.5 Q3.6 Q3.7 Q3.8 R90.2 R99.1 TP2.1 TP18.1 U1.4(VS)
VREF+: J12.B06 R50.2
VSNS1: C13.2 J12.A25 R29.2 R35.2 TP6.1
VSNS2: C14.2 J12.A26 R31.2 R37.2 TP7.1
VSNS3: C15.2 J12.A27 R33.2 R39.2 TP8.1
N341931: LED1.2 R2.1
N342654: R5.2 U1.2
N346164: C9.1 U1.17
N346292: C6.2 U1.21
N348026: R42.2 R44.1 R48.1 U2.5
N348030: R47.1 R53.2 R56.2 U2.6
N348034: R45.2 R53.1 R56.1 TP9.1 U2.7
N405802: Q4.4 R19.2 R22.2
N420950: C33.1 D7.1 L1.1 U5.8
N423156: C37.1 C38.2 R90.1 U5.5 U5.7(VIN)
N423472: C33.2 U5.1
N434416: J12.B12 R118.2
N443088: J12.A12 R117.1
N444531: D4.2 R22.1
N444693: D5.2 R23.1
N444697: Q5.4 R20.2 R23.2
N444879: D6.2 R24.1
N444883: Q6.4 R21.2 R24.2
N445065: D3.2 R15.1
N445069: Q3.4 R12.2 R15.2
N445327: D2.2 R14.1
N445331: Q2.4 R11.2 R14.2
N445554: D1.2 R13.1
N445558: Q1.4 R10.2 R13.2
N470361: C31.2 R81.1 TP14.1 U4.4
N471408: R73.1 R76.1 U2.10
N471412: R75.1 R77.1 U2.9
N471570: R74.2 R77.2 U2.8
N472042: J4.2 R81.2
N472470: C24.1 R55.1 R59.2 U3.3
N472582: R57.2 R58.2 R66.1
N478538: J6.1 R96.1 R101.2
N478542: J6.2 R97.1 R102.2
N478546: J6.3 R98.1 R104.2
N478738: C42.1 J5.2 J6.4
N479415: J9.1 R106.2
N479421: J9.2 R107.2
N479427: J9.3 R108.2
N479459: C48.1 J8.2 J9.4
N479601: J11.2 R114.2
N479607: J11.3 R115.2
N479625: J11.4 R116.2
N479657: C52.1 J10.2 J11.5
N479733: J11.1 R113.2
N480096: C51.2 R110.1 R111.2 U7.3
N487267: R28.2 R29.1
N487934: R30.2 R31.1
N488373: R32.2 R33.1
N490756: C22.2 R45.1 R46.1
N494551: R64.2 R70.1 R72.1 TP11.1 U2.1
N494643: R61.2 R63.1 R68.1 U2.3
N494647: R67.1 R70.2 R72.2 U2.2
N494767: C27.2 R64.1 R65.1
N495845: R82.2 R87.1 R89.1 TP13.1 U2.14(OUT)
N495931: R78.2 R80.1 R85.1 U2.12
N495935: R84.1 R87.2 R89.2 U2.13
N496035: C32.2 R82.1 R83.1
N496697: R50.1 R51.1 R52.1 R55.2
N501821: R99.2 R100.1
N513408: C8.1 U1.13
N519464: LED3.1 R105.2
N526328: LED2.2 R94.1
N526332: LED2.1 Q7.3
N574651: C49.2 R108.1 U6.9
N574774: C47.2 R107.1 U6.11
N574847: C46.2 R106.1 U6.14
N575649: R112.2 R114.1 U6.3
N599590: C16.2 R34.1
N599920: C17.2 R36.1
N600140: C18.2 R38.1
N605072: C25.2 R66.2 U3.4
N605096: C25.1 R58.1 U3.1

Pads without a net: J12 A03 A04 A09 A10 A11 A16 A30 A33 A34 A35 A36 A37 A38 A39 A40 A41 A42 A43 A44 A46 A47 A48 A50 A51 A52 A53 A54 A55 A57 A58 A59 A60 A61 A62 A63 A64 A66 A67 A68 A70 A71 A72 A73 A74 A75 A77 A78 A79 A80 A81 A82 B03 B04 B09 B10 B11 B29 B30 B33 B34 B35 B36 B37 B38 B39 B40 B41 B42 B43 B44 B46 B47 B48 B50 B51 B52 B53 B54 B55 B57 B58 B59 B60 B61 B62 B63 B64 B66 B67 B68 B70 B71 B72 B73 B74 B75 B77 B78 B79 B80 B81 B82; U6 4 6 13 16

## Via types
v1: diameter 0.65, hole 0.3, TOP to BOTTOM, 335 vias

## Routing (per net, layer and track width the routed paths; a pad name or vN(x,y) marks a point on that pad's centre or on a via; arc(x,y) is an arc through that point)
5V: length 209.7
  TOP w0.454: 26.72,16.29 J12.B05 ; J12.B05 26.72,17.76 ; J12.B05 28.18,17.76 ; J12.B05 28.18,16.29 ; 24.22,17.76 J12.A05 ; J12.A05 25.68,17.76 ; J12.A05 24.22,16.29 ; J12.A05 25.68,16.29
  TOP w0.635: R94.2 36.39,105.68 ; R92.2 TP15.1
  TOP w1.016: J8.1 J10.1 54.23,5.61 46.61,13.23 34.8,13.23 30.83,17.19
  TOP w1.905: TP15.1 29.97,105.68 13.84,89.55 13.84,22.01 v1(18.81,17.05)
  BOTTOM w0.454: 25.68,16.29 J12.A05 24.22,16.29 ; 28.18,16.29 J12.B05 26.72,16.29
  BOTTOM w0.508: 28.44,17.03 J12.B05 J12.A05 23.74,17.03
  BOTTOM w0.635: J10.1 71.37,3.95 77.72,3.95 87.5,13.73 J5.1
  vias: v1(18.8,15.77) v1(19.3,16.4) v1(19.3,15.13) v1(30.73,17.29) v1(30.73,16.27) v1(30.73,15.13)
12V: length 12.3
  TOP w0.33: U1.5 52.59,37.11 52.45,36.97
  TOP w0.508: C2.1 50.42,35.87 50.38,35.83 ; TP1.1 46.35,35.83 C1.2 50.38,35.83 ; 50.38,35.83 51.31,35.83 52.45,36.97
GND: length 19.8
  TOP w0.2: R27.1 66.09,31.46
  TOP w0.305: JP2.2 60.83,87.01
  TOP w0.508: R5.1 52.41,42.84 C5.1 v1(52.41,44.85) 52.41,45.71 R4.1 ; J2.2 56.04,48.31 C7.1
  TOP w0.635: R105.1 102.43,71.07 103,70.5 C16.1 C17.1 C18.1
  BOTTOM w0.305: JP2.2 60.83,87.27
  BOTTOM w0.454: 55.65,49.65 J2.2 ; J2.2 55.65,47.92 ; J2.2 57.38,47.92 ; J2.2 57.38,49.65
  vias: v1(47.37,42.63) v1(48.13,42.63) v1(49.66,38.37) v1(50.29,38.12) v1(54.74,38.88) v1(54.74,36.85) v1(55.75,37.86) v1(56.77,38.88) v1(56.77,36.85) v1(58.67,86.38) v1(59.56,86.38) v1(60.45,86.38) v1(61.34,86.38) v1(62.23,86.38) v1(63.12,86.38) v1(63.88,74.19) v1(63.88,73.3) v1(63.88,72.41) v1(63.88,71.52) v1(63.88,70.63) v1(63.88,53.61) v1(63.88,52.72) v1(63.88,51.83) v1(63.88,50.94) v1(63.88,50.06) v1(63.88,49.17) v1(63.88,32.4) v1(63.88,31.51) v1(63.88,30.62) v1(63.88,29.74) v1(63.88,28.85) v1(64.77,73.68) v1(64.77,72.79) v1(64.77,71.9) v1(64.77,71.01) v1(64.77,70.12) v1(64.77,53.1) v1(64.77,52.21) v1(64.77,51.33) v1(64.77,50.44) v1(64.77,49.55) v1(64.77,32.78) v1(64.77,31.89) v1(64.77,31.01) v1(64.77,30.12) v1(64.77,29.23) v1(65.53,69.36) v1(66.55,69.36) v1(67.18,70.12) v1(72.01,79.77) v1(72.01,78.76) v1(72.01,77.74) v1(72.01,76.73) v1(72.01,75.71) v1(72.01,74.69) v1(75.82,79.77) v1(75.82,78.76) v1(75.82,77.74) v1(75.82,76.73) v1(75.82,75.71) v1(75.82,74.69) v1(78.87,54.12) v1(78.87,40.4) v1(78.87,26.69) v1(79.63,54.5) v1(79.63,53.74) v1(79.63,40.78) v1(79.63,40.02) v1(79.63,27.07) v1(79.63,26.31)
GND_SIGNAL: length 202.5
  TOP w0.305: JP2.1 60.83,88.03
  TOP w0.381: v1(67.55,12.71) U6.8 U6.7 ; U2.11 v1(43.69,65.8) ; U6.5 v1(67.56,10.76)
  TOP w0.454: 26.72,79.76 J12.B65 ; J12.B65 26.72,78.29 ; J12.B65 28.18,78.29 ; J12.B65 28.18,79.76 ; 26.72,83.76 J12.B69 ; J12.B69 26.72,82.29 ; J12.B69 28.18,83.76 ; J12.B69 28.18,82.29 ; J12.A65 25.68,79.76 ; J12.A65 24.22,79.76 ; J12.A65 25.68,78.29 ; J12.A65 24.22,78.29 ; J12.A56 23.68,70.76 ; J12.A56 22.22,69.3 ; J12.A56 23.68,69.3 ; J12.A56 22.22,70.76 ; 28.72,70.76 J12.B56 30.18,70.76 ; J12.A76 23.68,90.76 ; J12.A76 22.22,89.29 ; J12.A76 22.22,90.76 ; J12.A76 23.68,89.29 ; J12.A69 25.68,83.76 ; J12.A69 25.68,82.29 ; J12.A69 24.22,82.29 ; J12.A69 24.22,83.76 ; 28.72,90.76 J12.B76 ; J12.B76 28.72,89.29 ; J12.B76 30.18,90.76 ; J12.B76 30.18,89.29
  TOP w0.508: v1(58.93,71.14) C22.1 58.13,72.57 R49.2 ; C44.2 v1(81.41,18.18) ; J9.5 49.4,18.65 C48.2 ; C45.2 v1(83.19,18.18) ; R85.2 36.89,66.82 R76.2 v1(37.91,67.64) ; R37.1 33.5,48.59 v1(33.53,48.62) C14.1 ; R103.1 v1(25.27,6.62) ; C47.1 v1(56.13,11.45) ; C20.2 v1(46.32,83.58) ; R86.2 37.88,59.03 v1(37.88,59.71) C32.1 ; J6.5 92.58,8.36 C42.2 ; C13.1 v1(33.53,45.95) 33.5,45.93 R35.1 ; C46.1 v1(56.13,9.67) ; C29.1 39.53,70.5 39.75,70.72 U4.2 v1(39.75,72.92) ; v1(58.93,60.47) C27.1 58.13,58.91 R69.2 ; C15.1 v1(33.53,51.29) 33.5,51.26 R39.1 ; J11.6 49.4,8.49 C52.2 ; C41.1 v1(23.5,6.62) ; C43.2 v1(79.63,18.18) ; 41.63,88.7 C23.2 41.66,88.28 v1(41.27,87.9) ; R48.2 v1(61.02,65.8) R68.2 ; C19.2 v1(52.96,82.57) ; C49.1 v1(56.13,13.23)
  TOP w0.635: C24.2 50.14,85.3 R59.1 48.2,85.3 v1(47.75,85.74) U3.2
  TOP w0.762: J12.B08 29.3,20.03 28.3,19.03 J12.B07 J12.A07
  BOTTOM w0.305: JP2.1 60.83,87.77
  BOTTOM w0.454: 28.18,19.76 J12.B07 26.72,19.76 ; 48.53,4.74 J11.6 ; J11.6 50.27,4.74 ; J11.6 48.53,6.47 ; J11.6 50.27,6.47 ; 26.72,59.76 J12.B45 ; J12.B45 26.72,58.3 ; J12.B45 28.18,59.76 ; J12.B45 28.18,58.3 ; 24.22,44.29 J12.A31 ; J12.A31 25.68,44.29 ; J12.A31 24.22,45.76 ; J12.A31 25.68,45.76 ; 26.72,39.76 J12.B25 ; J12.B25 26.72,38.29 ; J12.B25 28.18,38.29 ; J12.B25 28.18,39.76 ; J12.B27 28.18,40.29 ; J12.B27 28.18,41.76 ; J12.B27 26.72,40.29 ; J12.B27 26.72,41.76 ; 28.72,89.29 J12.B76 ; J12.B76 30.18,90.76 ; J12.B76 30.18,89.29 ; J12.B76 28.72,90.76 ; J12.B26 30.18,39.29 ; J12.B26 30.18,40.76 ; J12.B26 28.72,39.29 ; J12.B26 28.72,40.76 ; J12.B49 28.18,63.76 ; J12.B49 28.18,62.3 ; J12.B49 26.72,62.3 ; J12.B49 26.72,63.76 ; 22.22,34.76 J12.A20 ; J12.A20 23.68,33.29 ; J12.A20 22.22,33.29 ; J12.A20 23.68,34.76 ; J12.B69 28.18,83.76 ; J12.B69 26.72,83.76 ; J12.B69 26.72,82.29 ; J12.B69 28.18,82.29 ; J12.A32 23.68,45.29 ; J12.A32 23.68,46.76 ; J12.A32 22.22,45.29 ; J12.A32 22.22,46.76 ; J12.B32 30.18,46.76 ; J12.B32 28.72,45.29 ; J12.B32 30.18,45.29 ; J12.B32 28.72,46.76 ; J12.A49 25.68,63.76 ; J12.A49 24.22,62.3 ; J12.A49 25.68,62.3 ; J12.A49 24.22,63.76 ; J4.3 36.81,86.1 ; J4.3 35.07,84.37 ; J4.3 36.81,84.37 ; J4.3 35.07,86.1 ; J12.A45 25.68,59.76 ; J12.A45 24.22,58.3 ; J12.A45 25.68,58.3 ; J12.A45 24.22,59.76 ; 22.22,70.76 J12.A56 ; J12.A56 23.68,70.76 ; J12.A56 23.68,69.3 ; J12.A56 22.22,69.3 ; J12.B31 28.18,45.76 ; J12.B31 28.18,44.29 ; J12.B31 26.72,45.76 ; J12.B31 26.72,44.29 ; J12.A76 23.68,90.76 ; J12.A76 22.22,90.76 ; J12.A76 22.22,89.29 ; J12.A76 23.68,89.29 ; J12.A65 25.68,78.29 ; J12.A65 24.22,78.29 ; J12.A65 24.22,79.76 ; J12.A65 25.68,79.76 ; 22.22,37.29 J12.A24 ; J12.A24 22.22,38.76 ; J12.A24 23.68,38.76 ; J12.A24 23.68,37.29 ; 91.71,4.74 J6.5 ; J6.5 91.71,6.47 ; J6.5 93.45,6.47 ; J6.5 93.45,4.74 ; 26.72,78.29 J12.B65 ; J12.B65 28.18,78.29 ; J12.B65 28.18,79.76 ; J12.B65 26.72,79.76 ; 28.72,38.76 J12.B24 30.18,38.76 ; 28.72,70.76 J12.B56 ; J12.B56 30.18,69.3 ; J12.B56 30.18,70.76 ; J12.B56 28.72,69.3 ; J12.B08 30.18,19.29 ; J12.B08 28.72,19.29 ; J12.B08 30.18,20.76 ; J12.B08 28.72,20.76 ; J9.5 50.27,14.9 ; J9.5 50.27,16.63 ; J9.5 48.53,16.63 ; J9.5 48.53,14.9 ; 24.22,19.76 J12.A07 25.68,19.76 ; 24.22,83.76 J12.A69 ; J12.A69 24.22,82.29 ; J12.A69 25.68,83.76 ; J12.A69 25.68,82.29 ; 28.49,34.03 J12.B20
  BOTTOM w0.508: J12.B20 30.3,34.03
  vias: v1(15.75,88.79) v1(15.75,64.66) v1(18.67,64.66) v1(28.19,101.24) v1(32.26,86.25) v1(32.26,72.15) v1(36.07,20.72) v1(36.7,91.08) v1(37.21,101.24) v1(40.39,94.76) v1(45.21,101.24) v1(45.21,94.76) v1(48.01,98.44) v1(48.51,91.97) v1(50.93,96.03) v1(52.07,99.97) v1(53.72,99.97) v1(54.86,88.16) v1(55.37,99.97) v1(57.53,94.25) v1(58.42,88.66) v1(59.31,88.66) v1(60.2,88.66) v1(60.71,96.41) v1(60.71,93.36) v1(61.09,88.66) v1(61.72,94.89) v1(61.98,88.66) v1(62.74,96.41) v1(62.74,93.36) v1(62.87,88.66)
V1: length 29.4
  TOP w0.406: R28.1 104.52,26.18 106.43,28.08 106.43,51.07 104.14,53.36 103.76,53.36
V2: length 38.6
  TOP w0.406: R30.1 105.54,28.91 105.54,46.88 104.14,48.28 103.63,48.28
  TOP w0.508: R36.2 v1(104.65,62.88)
  BOTTOM w0.508: J3.2 104.65,50.94 v1(104.65,62.88)
V3: length 36.8
  TOP w0.406: R32.1 104.65,29.67 104.65,42.69 104.14,43.2 103.76,43.2
  TOP w0.508: R38.2 v1(106.3,62.88)
  BOTTOM w0.508: J3.3 106.3,47.51 v1(106.3,62.88)
VBUS: length 50.8
  TOP w0.406: 22.23,43.03 J12.A29
  TOP w0.508: R103.2 25.25,4.37 24.51,4.37 ; 24.51,4.37 24.38,4.25 TP19.1 R100.2 ; 24.51,4.37 C41.2 23.08,4.37 20.83,6.62 20.83,19.32 21.21,19.7 21.21,42 22.23,43.03
VDD: length 415.3
  TOP w0.305: v1(95.12,43.45) 93.34,43.45 92.77,44.02 NTC1.1
  TOP w0.381: 45.59,6.24 45.59,4.97 ; U6.1 v1(67.55,8.16)
  TOP w0.406: U7.5 v1(32,20.72)
  TOP w0.508: 45.59,4.97 45.59,3.07 ; R3.2 51.14,34.67 46.9,34.67 R2.2 ; R6.1 J1.1 ; D8.1 39.08,12.05 R112.1 39.4,12.05 D9.1 D10.1 44.74,12.05 45.59,11.19 45.59,6.24 ; J8.3 78.99,11.57 v1(79.63,11.57) R96.2 ; R97.2 v1(81.41,11.57) ; R98.2 v1(83.19,11.57)
  TOP w0.635: J1.1 47.37,49.67 47.37,46.5 48.07,45.8 R1.2 41.4,45.74 40.89,45.23 v1(40.89,36.97) v1(41.4,36.47) 41.53,36.34 44.39,36.34 R2.2 ; R51.2 50.55,83.96 49.02,83.96 48.07,83.01 R40.1 47.05,81.55 42.86,81.55 42.23,82.19 R41.1 41.78,82.57 37.63,78.41 C28.1 37.63,75.76 U4.5 38.76,74.59 35.56,71.39 35.56,54.5 v1(36.32,53.74) ; J10.3 77.22,3.19 92.46,3.19 93.98,4.72 93.98,14.37 J5.3 ; v1(32.38,23) R110.2
  TOP w0.762: J12.A06 21.72,16.79 21.72,13.23 31.88,3.07 72.26,3.07 J10.3 J8.3
  BOTTOM w0.254: v1(95.12,43.45) 95.63,43.45 97.54,41.55 97.54,20.34 96.52,19.32 37.19,19.32 37.06,19.19 33.53,19.19 v1(32,20.72)
  BOTTOM w0.381: J10.3 72.25,8.16 v1(67.55,8.16)
  BOTTOM w0.508: v1(79.63,11.57) v1(81.41,11.57) v1(83.19,11.57)
  BOTTOM w0.635: 36.32,54.25 v1(36.32,54.5) ; 36.32,54.25 39.24,51.33 J1.1 ; 36.32,54.25 v1(36.32,53.74) ; v1(32.38,23) 31.75,22.37 31.75,20.97 v1(32,20.72) 32.13,20.84 33.02,20.84 34.04,19.83 36.73,19.83 36.98,20.08 39.75,20.08 43.94,24.27 43.94,33.93 v1(41.4,36.47) v1(40.89,36.97)
  BOTTOM w0.762: v1(32,20.72) 31.97,20.69 31.97,19.61 33.91,17.67 72.9,17.67 J8.3
VDD_C: length 3.7
  TOP w0.508: U3.5 44.3,83.14 C20.1 R41.2
VDD_F: length 21.1
  TOP w0.381: 49.78,65.8 U2.4
  TOP w0.508: C19.1 50.71,74.98 47.88,72.15 47.88,67.71 49.78,65.8
  TOP w0.635: C19.1 R40.2
BUCK_OUT: length 7.6
  TOP w0.381: R91.2 v1(57.15,97.62)
  BOTTOM w0.381: v1(57.15,97.62) 57.15,102 v1(55.5,103.65)
CFBK: length 20
  TOP w0.305: v1(51.56,75.96) R60.1 53.59,77.36 TP12.1 ; C29.2 40.7,70.53 U4.3 42.96,72 R74.1 46.93,75.96 v1(49.66,75.96)
  BOTTOM w0.305: v1(51.56,75.96) v1(49.66,75.96)
CP_DRV: length 32.1
  TOP w0.305: R6.2 52.9,52.21 ; R6.2 J2.1 ; R6.2 52.9,50.6 52.89,50.59 52.89,49.83 C7.2 52.67,49.76 52.07,49.17 52.07,47.64 53.54,46.17 U1.1 ; 52.9,52.21 R9.1 R8.1 R7.1 ; 52.9,52.21 50.8,52.21 50.16,52.85 44.83,52.85 TP4.1
CURR_REF: length 44.7
  TOP w0.305: v1(31.93,42) 33.6,42 36.45,44.85 36.45,51.33 34.8,52.98 34.8,79.01 J4.1
  BOTTOM w0.305: J12.B28 30.51,42.03 30.54,42 v1(31.93,42)
ENCA: length 52.4
  TOP w0.305: U6.15 61.37,8.81 62.61,10.05 62.61,14.24 v1(62.1,14.75) ; v1(36.83,26.05) 37.08,26.31 38.61,26.31 39.62,25.29 46.99,25.29 54.36,17.92 59.05,17.92 v1(60.45,16.53)
  BOTTOM w0.305: J12.B16 30.9,30.03 33.27,32.4 35.94,32.4 37.21,31.13 37.21,26.43 v1(36.83,26.05) ; v1(62.1,14.75) 62.1,14.88 v1(60.45,16.53)
ENCB: length 51.3
  TOP w0.305: v1(59.44,16.53) 58.67,17.29 54.23,17.29 46.74,24.78 39.37,24.78 38.61,25.54 v1(37.72,25.54) ; U6.12 61.41,10.76 62.1,11.45 62.1,13.73 v1(61.09,14.75)
  BOTTOM w0.305: J12.B17 31.14,31.03 33.02,32.91 36.2,32.91 37.85,31.26 37.85,25.67 v1(37.72,25.54) ; v1(59.44,16.53) 61.09,14.88 v1(61.09,14.75)
ENCZ: length 47.6
  TOP w0.305: v1(38.23,24.78) 38.73,24.27 46.48,24.27 54.23,16.53 v1(58.42,16.53) ; v1(60.07,14.75) 61.59,13.23 61.59,12.36 61.29,12.06 U6.10
  BOTTOM w0.305: v1(38.23,24.78) 38.48,25.04 38.48,31.39 36.45,33.42 32.77,33.42 31.37,32.03 J12.B18 ; v1(60.07,14.75) 58.42,16.4 v1(58.42,16.53)
ETR: length 59.4
  TOP w0.305: U4.1 38.78,72.03 v1(37.97,72.03) ; v1(33.35,70.48) 33.35,70.07 30.3,67.02 28.93,67.02 27.94,66.03 24.46,66.03 23.47,65.04 22.3,65.04 20.09,62.83 v1(20.09,31.06)
  BOTTOM w0.305: v1(33.35,70.48) 34.9,72.03 v1(37.97,72.03) ; J12.A17 20.12,31.03 v1(20.09,31.06)
FB: length 17.3
  TOP w0.381: R95.2 R93.1 49.38,102.29 48.64,102.29 ; 48.64,102.29 v1(48.64,101.74) ; 48.64,102.29 C36.1 ; U5.4 v1(57.53,92.98)
  BOTTOM w0.381: v1(57.53,92.98) 48.77,101.74 v1(48.64,101.74)
GHS1: length 34.7
  TOP w0.33: U1.22 55.5,41.68 v1(55.75,41.93)
  TOP w0.406: R10.1 78.14,58.82 D1.1 v1(77.22,58.79)
  BOTTOM w0.406: v1(77.22,58.79) 77.22,55.52 65.53,43.83 57.66,43.83 v1(55.75,41.93)
GHS2: length 24.1
  TOP w0.33: U1.18 58.91,39.11 v1(59.18,39.39)
  TOP w0.406: R11.1 78.14,45.1 D2.1 v1(77.25,45.07)
  BOTTOM w0.406: v1(77.25,45.07) 71.56,39.39 v1(59.18,39.39)
GHS3: length 24
  TOP w0.33: U1.14 58.92,37.11 v1(59.18,36.85)
  TOP w0.406: v1(77.25,31.35) D3.1 78.14,31.39 R12.1
  BOTTOM w0.406: v1(59.18,36.85) 60.33,35.7 72.39,35.7 76.74,31.35 v1(77.25,31.35)
GLS1: length 39.5
  TOP w0.33: v1(59.18,45.48) 55.88,45.48 54.5,44.11 U1.24
  TOP w0.406: R19.1 78.14,62.37 D4.1 v1(77.25,62.34)
  BOTTOM w0.406: v1(77.25,62.34) 75.72,60.81 75.72,56.05 65.15,45.48 v1(59.18,45.48)
GLS2: length 27.1
  TOP w0.33: v1(59.18,41.42) 58.93,41.17 56.83,41.17 56.5,40.83 U1.20
  TOP w0.406: v1(77.25,48.63) D5.1 78.14,48.66 R20.1
  BOTTOM w0.406: v1(77.25,48.63) 70.04,41.42 v1(59.18,41.42)
GLS3: length 22.9
  TOP w0.33: v1(61.85,37.86) 61.6,38.11 U1.16
  TOP w0.406: v1(77.22,34.91) D6.1 78.14,34.94 R21.1
  BOTTOM w0.406: v1(61.85,37.86) 74.26,37.86 v1(77.22,34.91)
H1: length 72.3
  TOP w0.305: R101.1 C43.1 79.34,15.8 76.45,18.69 59.82,18.69 58.42,20.08 58.42,23.13 55.5,26.05 39.75,26.05 38.99,26.81 v1(36.32,26.81)
  BOTTOM w0.305: v1(36.32,26.81) 36.58,27.07 36.58,31.01 35.69,31.89 33.53,31.89 30.61,28.97 29.01,28.97 27.97,30.01 26.87,30.01 26.21,30.67 26.21,31.34 25.52,32.03 J12.A18
H2: length 71.8
  TOP w0.305: R102.1 C44.1 81.12,15.8 80.52,16.4 80.52,18.43 79.76,19.19 60.07,19.19 58.93,20.34 58.93,23.34 55.71,26.56 40.26,26.56 v1(40.01,26.81) ; v1(31.29,33.01) 28.96,33.01 27.97,32.02 25.95,32.02 J12.A19
  BOTTOM w0.305: v1(31.29,33.01) 32.21,33.93 36.7,33.93 40.01,30.62 v1(40.01,26.81)
H3: length 70.5
  TOP w0.305: v1(40.77,27.32) 41.02,27.07 55.92,27.07 59.44,23.55 59.44,20.59 60.33,19.7 81.15,19.7 82.3,18.56 82.3,16.4 82.89,15.8 C45.1 R104.1
  BOTTOM w0.305: v1(40.77,27.32) 40.77,30.62 36.96,34.43 31.72,34.43 30.32,33.03 J12.B19
ID_ENABLE_N: length 11
  TOP w0.305: J12.A08 27.93,20.03 28.93,21.02 30.35,21.02 31.42,19.96 32.92,19.96 U7.6
INH1: length 35.5
  TOP w0.254: U1.7 54.5,34.2 51.82,31.51 41.15,31.51 41.02,31.64 35.18,31.64 v1(34.67,31.13) ; J12.A13 25.92,26.05 27.97,26.05 28.93,27.02 31.47,27.02 v1(31.5,26.99)
  BOTTOM w0.254: v1(34.67,31.13) 34.67,30.17 v1(31.5,26.99)
INH2: length 39.7
  TOP w0.254: v1(35.56,31.01) 52.02,31.01 55,33.99 U1.8 ; v1(31.11,25.29) 30.86,25.04 25.45,25.04 22.95,27.54 J12.A14
  BOTTOM w0.254: v1(31.11,25.29) 35.56,29.74 v1(35.56,31.01)
INH3: length 34.9
  TOP w0.254: U1.9 55.5,33.79 52.08,30.36 34.43,30.36 33.76,31.03 28.96,31.03 27.97,30.04 25.96,30.04 J12.A15
INL1: length 33.6
  TOP w0.254: U1.10 56,33.58 52.29,29.86 33.78,29.86 v1(33.53,30.12)
  BOTTOM w0.254: J12.B13 30.56,27.03 33.53,29.99 v1(33.53,30.12)
INL2: length 31.7
  TOP w0.254: U1.11 56.5,33.37 52.53,29.4 32.47,29.4 v1(32.26,29.61)
  BOTTOM w0.254: v1(32.26,29.61) 30.68,28.03 J12.B14
INL3: length 33.8
  TOP w0.254: J12.B15 30,29.03 30.05,28.97 52.81,28.97 57,33.16 U1.12
ISNS1N: length 60.3
  TOP w0.305: J12.B21 32.72,35.03 39.97,42.28 39.97,51.55 42.8,54.37 43.94,54.37 45.97,56.41 51.75,56.41 v1(51.94,56.6) ; 56.77,74.19 56.77,72.66 v1(55.88,72.66)
  BOTTOM w0.305: v1(51.94,56.6) 51.94,70.95 53.66,72.66 v1(55.88,72.66)
ISNS1P: length 60.3
  TOP w0.305: v1(31.11,35.78) 32.72,35.78 39.49,42.56 39.49,51.83 42.52,54.86 43.68,54.86 45.74,56.91 50.99,56.91 v1(51.18,57.1) ; v1(52.7,72.66) R46.2 R43.2
  BOTTOM w0.305: J12.A21 25.96,36.03 27.97,36.03 28.98,35.02 30.35,35.02 v1(31.11,35.78) ; v1(52.7,72.66) 52.7,72.41 51.44,71.14 51.44,57.36 v1(51.18,57.1)
ISNS2N: length 44
  TOP w0.305: J12.B22 29.94,36.52 31.93,36.52 38.89,43.48 38.89,52.24 42.04,55.39 43.05,55.39 45.47,57.8 51.75,57.8 53.15,56.41 56.01,56.41 56.77,57.17 56.77,58.82
ISNS2P: length 68.5
  TOP w0.305: R60.2 v1(57.02,75.96) ; J12.A22 27.96,36.03 28.96,37.02 31.67,37.02 38.35,43.71 38.35,52.47 41.78,55.9 42.8,55.9 45.21,58.31 52.01,58.31 53.02,57.29 R62.2 v1(53.59,58.06) R65.2
  BOTTOM w0.305: v1(53.59,58.06) 53.59,68.53 57.15,72.09 57.15,75.84 v1(57.02,75.96)
ISNS3N: length 28.6
  TOP w0.305: v1(32,39.77) 32.32,39.77 37.21,44.66 37.21,54.94 39.24,56.98 39.24,58.95
  BOTTOM w0.305: v1(32,39.77) 32,38.78 30.25,37.03 J12.B23
ISNS3P: length 33.7
  TOP w0.305: J12.A23 25.94,38.02 27.94,38.02 28.96,39.03 32.3,39.03 37.72,44.45 37.72,54.75 39.43,56.47 41.91,56.47 42.42,56.98 R79.2 R83.2
NFAULT: length 33
  TOP w0.305: 50.04,33.15 50.04,33.48 LED1.1 49.97,33.09 ; 50.04,33.15 50.34,32.85 R3.1 51.75,32.85 53.54,34.64 U1.6 ; 50.04,33.15 49.97,33.09 ; 49.97,33.09 48.91,32.02 45.72,32.02 v1(45.47,32.28) 43.94,33.8 TP3.1 ; R117.2 R118.1 34.67,27.07 35.94,28.34 v1(45.47,28.34)
  BOTTOM w0.305: v1(45.47,32.28) v1(45.47,28.34)
OPREF: length 82.7
  TOP w0.305: R78.1 v1(40.26,64.79)
  TOP w0.381: TP10.1 43.43,92.73 R57.1 ; v1(58.17,77.11) 58.29,77.23 58.29,83.39 50.48,91.2 45.47,91.2 44.96,90.7 R52.2 44.7,90.06 R57.1 ; R57.1 41.75,90.06 C23.1 41.63,90.12 38.73,90.12 34.16,85.55 34.16,64.91 v1(34.04,64.79) ; R61.1 v1(55.75,64.79) ; R42.1 v1(55.75,66.82)
  BOTTOM w0.381: v1(58.17,77.11) 58.17,71.39 55.75,68.98 v1(55.75,66.82) v1(55.75,64.79) ; v1(40.26,64.79) v1(34.04,64.79)
OUT1: length 40.2
  TOP w0.33: C6.1 55,42.69 U1.23
  TOP w0.406: R16.1 82.55,60.72 81.66,59.83 v1(77.22,59.83) ; C6.1 55.51,43.85 56.26,44.59 v1(59.18,44.59)
  BOTTOM w0.406: v1(77.22,59.83) 76.96,59.83 76.48,59.35 76.48,55.8 65.28,44.59 v1(59.18,44.59)
OUT2: length 29
  TOP w0.33: U1.19 57,40.2 57.33,40.53 60.34,40.53 C9.2 61.48,40.9 61.85,40.53 v1(61.85,40.4)
  TOP w0.406: v1(77.22,46.12) 81.66,46.12 82.55,47.01 R17.1
  BOTTOM w0.406: v1(61.85,40.4) 71.5,40.4 v1(77.22,46.12)
OUT3: length 27.2
  TOP w0.33: U1.15 59.93,37.61 C8.2 v1(61.86,36.83)
  TOP w0.406: v1(77.22,32.4) 81.66,32.4 82.55,33.29 R18.1
  BOTTOM w0.406: v1(77.22,32.4) 72.78,36.83 v1(61.86,36.83)
P_GOOD: length 7.9
  TOP w0.381: U5.2 56.96,95.52 R91.1 54.74,96.22 Q7.1 54.5,94.39 TP17.1
SCREF: length 14.1
  TOP w0.305: 51.94,38.63 52.46,38.11 U1.3
  TOP w0.508: J1.2 49.47,48.34 R1.1 R4.2 50.96,45.71 C5.2 51.18,43.74 51.18,39.39 51.94,38.63
SHUNT1N: length 21.1
  TOP w0.305: R47.2 56.54,69.58 C21.1 58.38,69.36 v1(59.56,69.36) 59.82,69.61 59.82,73.17 58.8,74.19 R54.2 ; JP3.2 68.45,70.68 v1(68.45,70.63)
  BOTTOM w0.305: v1(68.45,70.63) 68.45,69.49 67.06,68.09 60.96,68.09 59.69,69.36 v1(59.56,69.36)
SHUNT1P: length 48.9
  TOP w0.305: 59.94,68.47 v1(59.56,68.47) 58.51,68.47 C21.2 58.1,68.06 R44.2 ; 59.94,68.47 60.33,68.85 60.33,73.42 58.67,75.07 55.75,75.07 R43.1 ; 59.94,68.47 60.96,68.47 61.98,67.45 61.98,59.58 v1(58.67,56.28) ; 55.56,54.63 v1(56.52,54.63) ; v1(69.34,70.25) 70.74,71.65 R25.2
  BOTTOM w0.305: v1(56.52,54.63) 58.17,56.28 v1(58.67,56.28) ; v1(59.56,68.47) 59.82,68.47 60.71,67.58 67.31,67.58 69.34,69.61 v1(69.34,70.25)
SHUNT2N: length 65.4
  TOP w0.305: v1(49.28,59.07) 49.28,59.2 46.74,61.74 46.74,68.09 46.1,68.72 44.83,68.72 v1(44.07,69.49) ; 58.46,62.03 58.64,62.03 59.69,60.98 59.69,58.95 R71.2 ; 58.46,62.03 C26.1 56.54,62.03 R67.2 ; 58.46,62.03 58.93,62.5 60.33,62.5 v1(60.45,62.37) ; R75.2 v1(38.61,68.34) ; JP4.2 68.58,52.47 68.58,53.61 v1(68.33,53.87)
  BOTTOM w0.305: v1(38.61,68.34) 43.18,68.34 44.07,69.23 v1(44.07,69.49) ; v1(68.33,53.87) 68.2,53.99 68.2,54.88 60.71,62.37 v1(60.45,62.37) 60.2,62.12 60.2,59.96 56.9,56.66 55.88,56.66 53.09,53.87 50.42,53.87 49.78,54.5 49.78,58.56 v1(49.28,59.07)
SHUNT2P: length 61.8
  TOP w0.305: v1(68.96,54.63) 69.34,54.25 69.34,52.85 70.61,51.58 71.5,51.58 ; v1(49.53,59.96) 49.28,59.96 47.24,61.99 47.24,68.34 46.1,69.49 v1(45.09,69.49) ; R63.2 58.1,63.54 C26.2 58.46,63.48 58.8,63.14 60.33,63.14 v1(60.41,63.23) ; v1(40.26,67.45) 40.89,66.82 R73.2 ; R62.1 v1(55.75,57.29) ; 51.5,54.63 v1(50.67,54.63)
  BOTTOM w0.305: v1(68.96,54.63) 68.96,54.88 60.71,63.14 60.5,63.14 v1(60.41,63.23) 60.16,63.23 59.69,62.76 59.69,60.22 56.77,57.29 v1(55.75,57.29) 53.09,54.63 v1(50.67,54.63) 50.29,55.01 50.29,59.2 v1(49.53,59.96) ; v1(45.09,69.49) 43.43,67.84 40.64,67.84 v1(40.26,67.45)
SHUNT3N: length 64
  TOP w0.305: v1(45.97,55.01) 46.1,54.88 47.12,54.88 47.62,55.39 57.53,55.39 62.61,50.31 62.61,35.07 61.98,34.43 v1(61.98,33.93) ; R88.2 36.96,58.44 v1(36.96,62.03) C30.1 39.47,62.03 R84.2 ; v1(68.71,32.4) JP5.2
  BOTTOM w0.305: v1(61.98,33.93) 62.36,33.55 67.44,33.55 68.58,32.4 v1(68.71,32.4) ; v1(45.97,55.01) 45.97,55.26 38.73,62.5 37.43,62.5 v1(36.96,62.03)
SHUNT3P: length 83.8
  TOP w0.305: v1(45.21,54.12) 45.72,53.61 50.8,53.61 51.44,52.98 R9.2 ; v1(62.87,34.31) 63.12,34.56 63.12,50.52 57.74,55.9 46.86,55.9 v1(46.61,55.64) ; R80.2 37.91,63.54 C30.2 37.43,63.48 v1(36.96,63.01) ; R79.1 v1(40.26,57.42) ; v1(68.71,33.29) 68.96,33.29 70.99,31.26 R27.2
  BOTTOM w0.305: v1(45.21,54.12) 41.91,57.42 v1(40.26,57.42) 40.26,59.45 38.35,61.36 36.58,61.36 36.26,61.68 36.26,62.7 36.56,63.01 v1(36.96,63.01) 38.99,63.01 46.35,55.64 v1(46.61,55.64) ; v1(68.71,33.29) 68.45,33.29 67.69,34.05 63.12,34.05 v1(62.87,34.31)
SPI_MISO: length 42.2
  TOP w0.305: J12.B01 29.16,11.32 v1(34.67,11.32) ; v1(51.56,9.8) 51.69,9.67 51.69,9.54 54.48,6.75 62.87,6.75 64.92,8.81 U6.2
  BOTTOM w0.305: v1(34.67,11.32) 36,9.99 51.37,9.99 v1(51.56,9.8)
SPI_MOSI: length 15.1
  TOP w0.305: v1(35.69,11.32) 34.92,12.08 31.39,12.08 J12.B02 ; R115.1 D9.2 41.37,10.59 v1(40.74,11.22)
  BOTTOM w0.305: v1(35.69,11.32) 35.81,11.45 40.51,11.45 v1(40.74,11.22)
SPI_NSS: length 14
  TOP w0.305: R113.1 D8.2 27.39,10.59 J12.A01
SPI_SCK: length 32.2
  TOP w0.305: J12.A02 22.95,13.14 31.88,4.21 42.42,4.21 43.05,4.84 43.05,9.29 43.69,9.92 44.32,9.92 ; 44.32,9.92 D10.2 ; 44.32,9.92 R116.1
TEMP_ID: length 29.9
  TOP w0.305: J12.A28 21.87,40.94 21.87,25.49 23.34,24.02 29.4,24.02 31.94,21.48 32.92,21.48 U7.4
TPCB: length 98.9
  TOP w0.305: v1(95.12,44.34) NTC1.2
  TOP w0.381: 37.8,18.72 C50.2 36.38,18.72 U7.1 ; 37.8,18.72 37.83,18.69 v1(37.85,18.69) 39.2,18.69 42.76,22.24 TP21.1 ; 37.8,18.72 38.66,18.72 38.68,18.75 R109.2
  BOTTOM w0.254: v1(95.12,44.34) 95.38,44.34 98.04,41.67 98.04,20.08 96.77,18.81 37.97,18.81 v1(37.85,18.69)
VM: length 90.4
  TOP w0.33: 52.07,37.61 U1.4
  TOP w0.381: TP2.1 44.2,44.85 48.89,44.85 49.64,44.1 C4.2
  TOP w0.508: LED3.2 105.41,82.06 104.52,82.95 ; 52.07,37.61 51.94,37.61 50.42,39.13 50.42,40.77 C3.2
  TOP w0.635: v1(49.66,42.56) 49.66,41.56 C3.2 C4.2
  TOP w0.962: 100.35,86.78 J7.1 ; J7.1 100.35,83.53 ; J7.1 103.61,83.53 ; J7.1 103.61,86.78
  BOTTOM w0.635: 82.75,25.73 82.75,24.98 82.3,24.53 61.98,24.53 48.64,37.86 48.64,41.55 v1(49.66,42.56)
  BOTTOM w0.962: 100.35,83.53 J7.1 ; J7.1 100.35,86.78 ; J7.1 103.61,86.78 ; J7.1 103.61,83.53
  vias: v1(72.14,89.93) v1(72.14,87.39) v1(72.14,84.85) v1(73.02,83.96) v1(73.91,83.96) v1(74.8,83.96) v1(75.69,89.93) v1(75.69,87.39) v1(75.69,84.85) v1(83.19,55.52) v1(83.19,41.8) v1(83.19,28.08) v1(83.31,57.93) v1(83.31,44.21) v1(83.31,30.5) v1(83.95,55.52) v1(83.95,41.8) v1(83.95,28.08) v1(84.58,54.5) v1(84.58,53.74) v1(84.58,40.78) v1(84.58,40.02) v1(84.58,27.07) v1(84.58,26.31) v1(84.71,55.52) v1(84.71,41.8) v1(84.71,28.08) v1(85.09,57.93) v1(85.09,44.21) v1(85.09,30.5) v1(85.47,55.52) v1(85.47,41.8) v1(85.47,28.08) v1(86.23,89.93) v1(86.23,87.39) v1(86.23,84.85) v1(86.36,57.8) v1(86.36,57.04) v1(86.36,56.28) v1(86.36,55.52) v1(86.36,44.09) v1(86.36,43.32) v1(86.36,42.56) v1(86.36,41.8) v1(86.36,30.37) v1(86.36,29.61) v1(86.36,28.85) v1(86.36,28.08) v1(87.12,83.96) v1(88.01,83.96) v1(88.52,57.8) v1(88.52,53.48) v1(88.52,44.09) v1(88.52,39.77) v1(88.52,30.37) v1(88.52,26.05) v1(88.9,83.96) v1(89.79,89.93) v1(89.79,87.39) v1(89.79,84.85) v1(90.68,57.17) v1(90.68,53.48) v1(90.68,44.09) v1(90.68,39.77) v1(90.68,30.37) v1(90.68,26.05) v1(92.84,54.88) v1(92.84,53.48) v1(92.84,30.37) v1(92.84,26.05) v1(92.96,41.93)
VREF+: length 107
  TOP w0.305: v1(20.33,20.86) 20.57,21.1 20.57,28.95 19.2,30.32 19.2,63.95 22.28,67.02 23.47,67.02 24.49,68.04 27.97,68.04 28.93,69 30.3,69 33.4,72.1 33.4,85.61 38.86,91.08 v1(42.55,91.08) ; R50.2 v1(51.05,88.54)
  BOTTOM w0.305: v1(20.33,20.86) 22.2,18.99 23.47,18.99 24.44,18.03 J12.B06 ; v1(42.55,91.08) 45.09,88.54 v1(51.05,88.54)
VSNS1: length 45.6
  TOP w0.305: J12.A25 25.7,39.03 26.7,40.02 27.97,40.02 28.98,41.04 29.92,41.04 32.77,43.88 R35.2 32.79,44.5 C13.2 34.96,44.5 v1(35.56,45.1) ; R29.2 v1(53.72,22.5)
  BOTTOM w0.305: v1(35.56,45.1) 35.56,44.47 53.72,26.31 v1(53.72,22.5)
VSNS2: length 56.1
  TOP w0.305: R31.2 v1(61.72,22.5) ; v1(35.56,46.12) 35.56,46.25 34.63,47.17 C14.2 32.79,47.17 R37.2 32.45,47.2 31.75,46.5 31.75,44.59 30.18,43.02 28.93,43.02 27.94,42.03 26.77,42.03 26.21,41.47 26.21,40.63 25.61,40.03 J12.A26
  BOTTOM w0.305: v1(61.72,22.5) 58.29,22.5 36.35,44.44 36.35,45.33 v1(35.56,46.12)
VSNS3: length 65.8
  TOP w0.305: 34.44,49.86 34.44,49.86 C15.2 ; 34.44,49.86 34.73,49.86 35.69,48.91 v1(35.69,47.13) ; 34.44,49.86 R39.2 32.45,49.86 30.99,48.4 30.99,45.84 30.18,45.03 28.93,45.03 27.93,44.02 26.76,44.02 26.21,43.48 26.21,42.54 24.95,41.27 J12.A27 ; R33.2 v1(69.72,22.5)
  BOTTOM w0.305: v1(35.69,47.13) 36.96,45.86 36.96,44.57 58.27,23.26 68.96,23.26 v1(69.72,22.5)
N341931: length 1.9
  TOP w0.305: LED1.2 47.36,32.84 46.49,32.84 R2.1
N342654: length 3.6
  TOP w0.305: U1.2 52.72,38.61 52.5,38.83 52.5,39.08 52.07,39.51 R5.2
N346164: length 3
  TOP w0.33: C9.1 60.17,38.61 U1.17
N346292: length 3.6
  TOP w0.33: C6.2 57.26,42.42 56,41.16 U1.21
N348026: length 10.4
  TOP w0.305: R48.1 58.86,66.06 57.28,66.06 56.71,66.63 R44.1 55.94,66.06 54.1,66.06 53.53,66.63 R42.2 53.16,66.45 U2.5
N348030: length 7.7
  TOP w0.305: R53.2 R56.2 ; R53.2 54.96,68.13 53.34,68.13 52.32,67.1 U2.6 ; R53.2 R47.1
N348034: length 1.7
  TOP w0.305: R53.1 53.37,69.55 53.34,69.58
N405802: length 3.5
  TOP w0.406: R22.2 R19.2 81.13,62.54 Q4.4
N423156: length 6.7
  TOP w0.508: 68.07,92.98 68.45,93.36 68.45,95.27 67.96,95.76 C37.1 66.69,95.52 U5.7
N423472: length 10.7
  TOP w0.381: U5.1 v1(58.98,97.43) ; v1(66.93,100.09) C33.2
  BOTTOM w0.381: v1(58.98,97.43) 61.65,100.09 v1(66.93,100.09)
N434416: length 4
  TOP w0.305: R118.2 30.54,26.05 30.51,26.03 J12.B12
N443088: length 11.1
  TOP w0.254: R117.1 24.45,24.53 J12.A12
N444531: length 1.5
  TOP w0.406: D4.2 78.14,60.85 R22.1
N444693: length 1.5
  TOP w0.406: R23.1 78.14,47.13 D5.2
N444697: length 3.5
  TOP w0.406: R23.2 R20.2 81.13,48.83 Q5.4
N444879: length 1.5
  TOP w0.406: D6.2 78.14,33.42 R24.1
N444883: length 3.5
  TOP w0.406: Q6.4 81.13,35.11 R21.2 R24.2
N445065: length 1.5
  TOP w0.406: R15.1 78.14,29.86 D3.2
N445069: length 3.9
  TOP w0.406: R15.2 R12.2 81.27,31.7 Q3.4
N445327: length 1.5
  TOP w0.406: D2.2 78.14,43.58 R14.1
N445331: length 3.9
  TOP w0.406: R14.2 R11.2 81.27,45.41 Q2.4
N445554: length 1.5
  TOP w0.406: R13.1 78.14,57.29 D1.2
N445558: length 3.9
  TOP w0.406: R13.2 R10.2 81.27,59.13 Q1.4
